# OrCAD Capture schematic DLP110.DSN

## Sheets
1 PAGE-10 Important Notice
2 PAGE-09 Rev History
3 PAGE-01  TITLE: rev: D
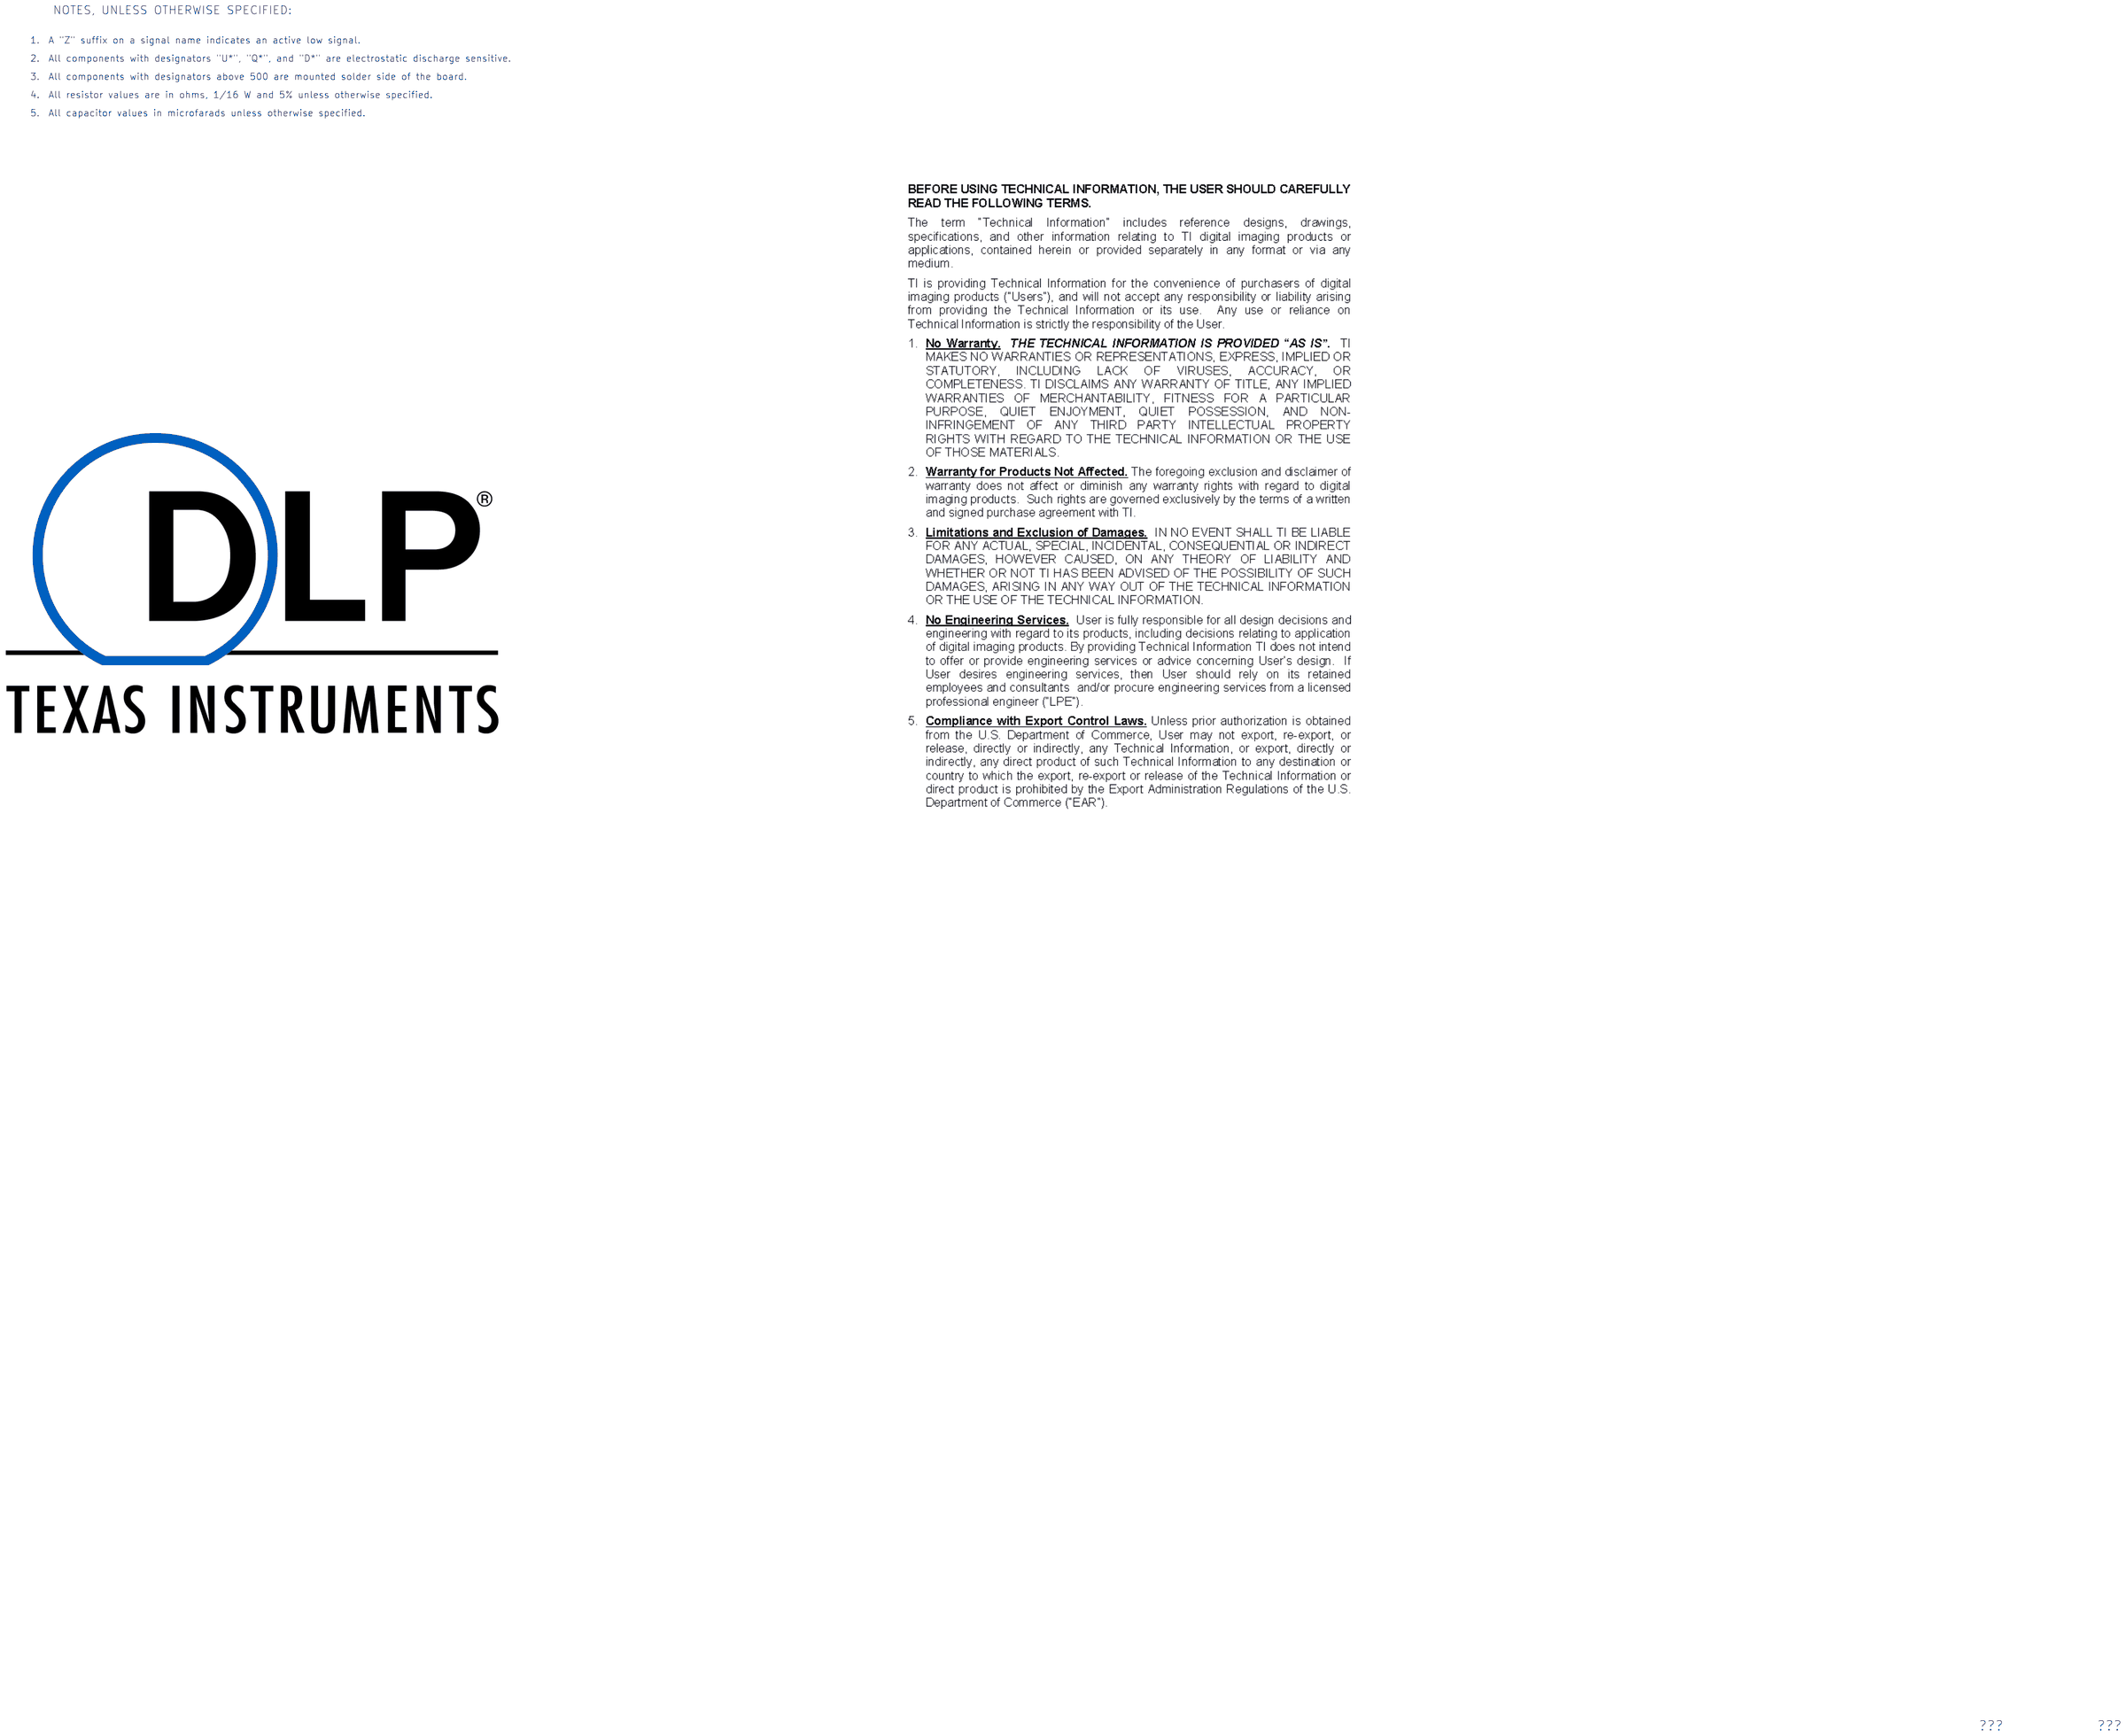
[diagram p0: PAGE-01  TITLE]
4 PAGE-02  BLOCK DIAGRAM
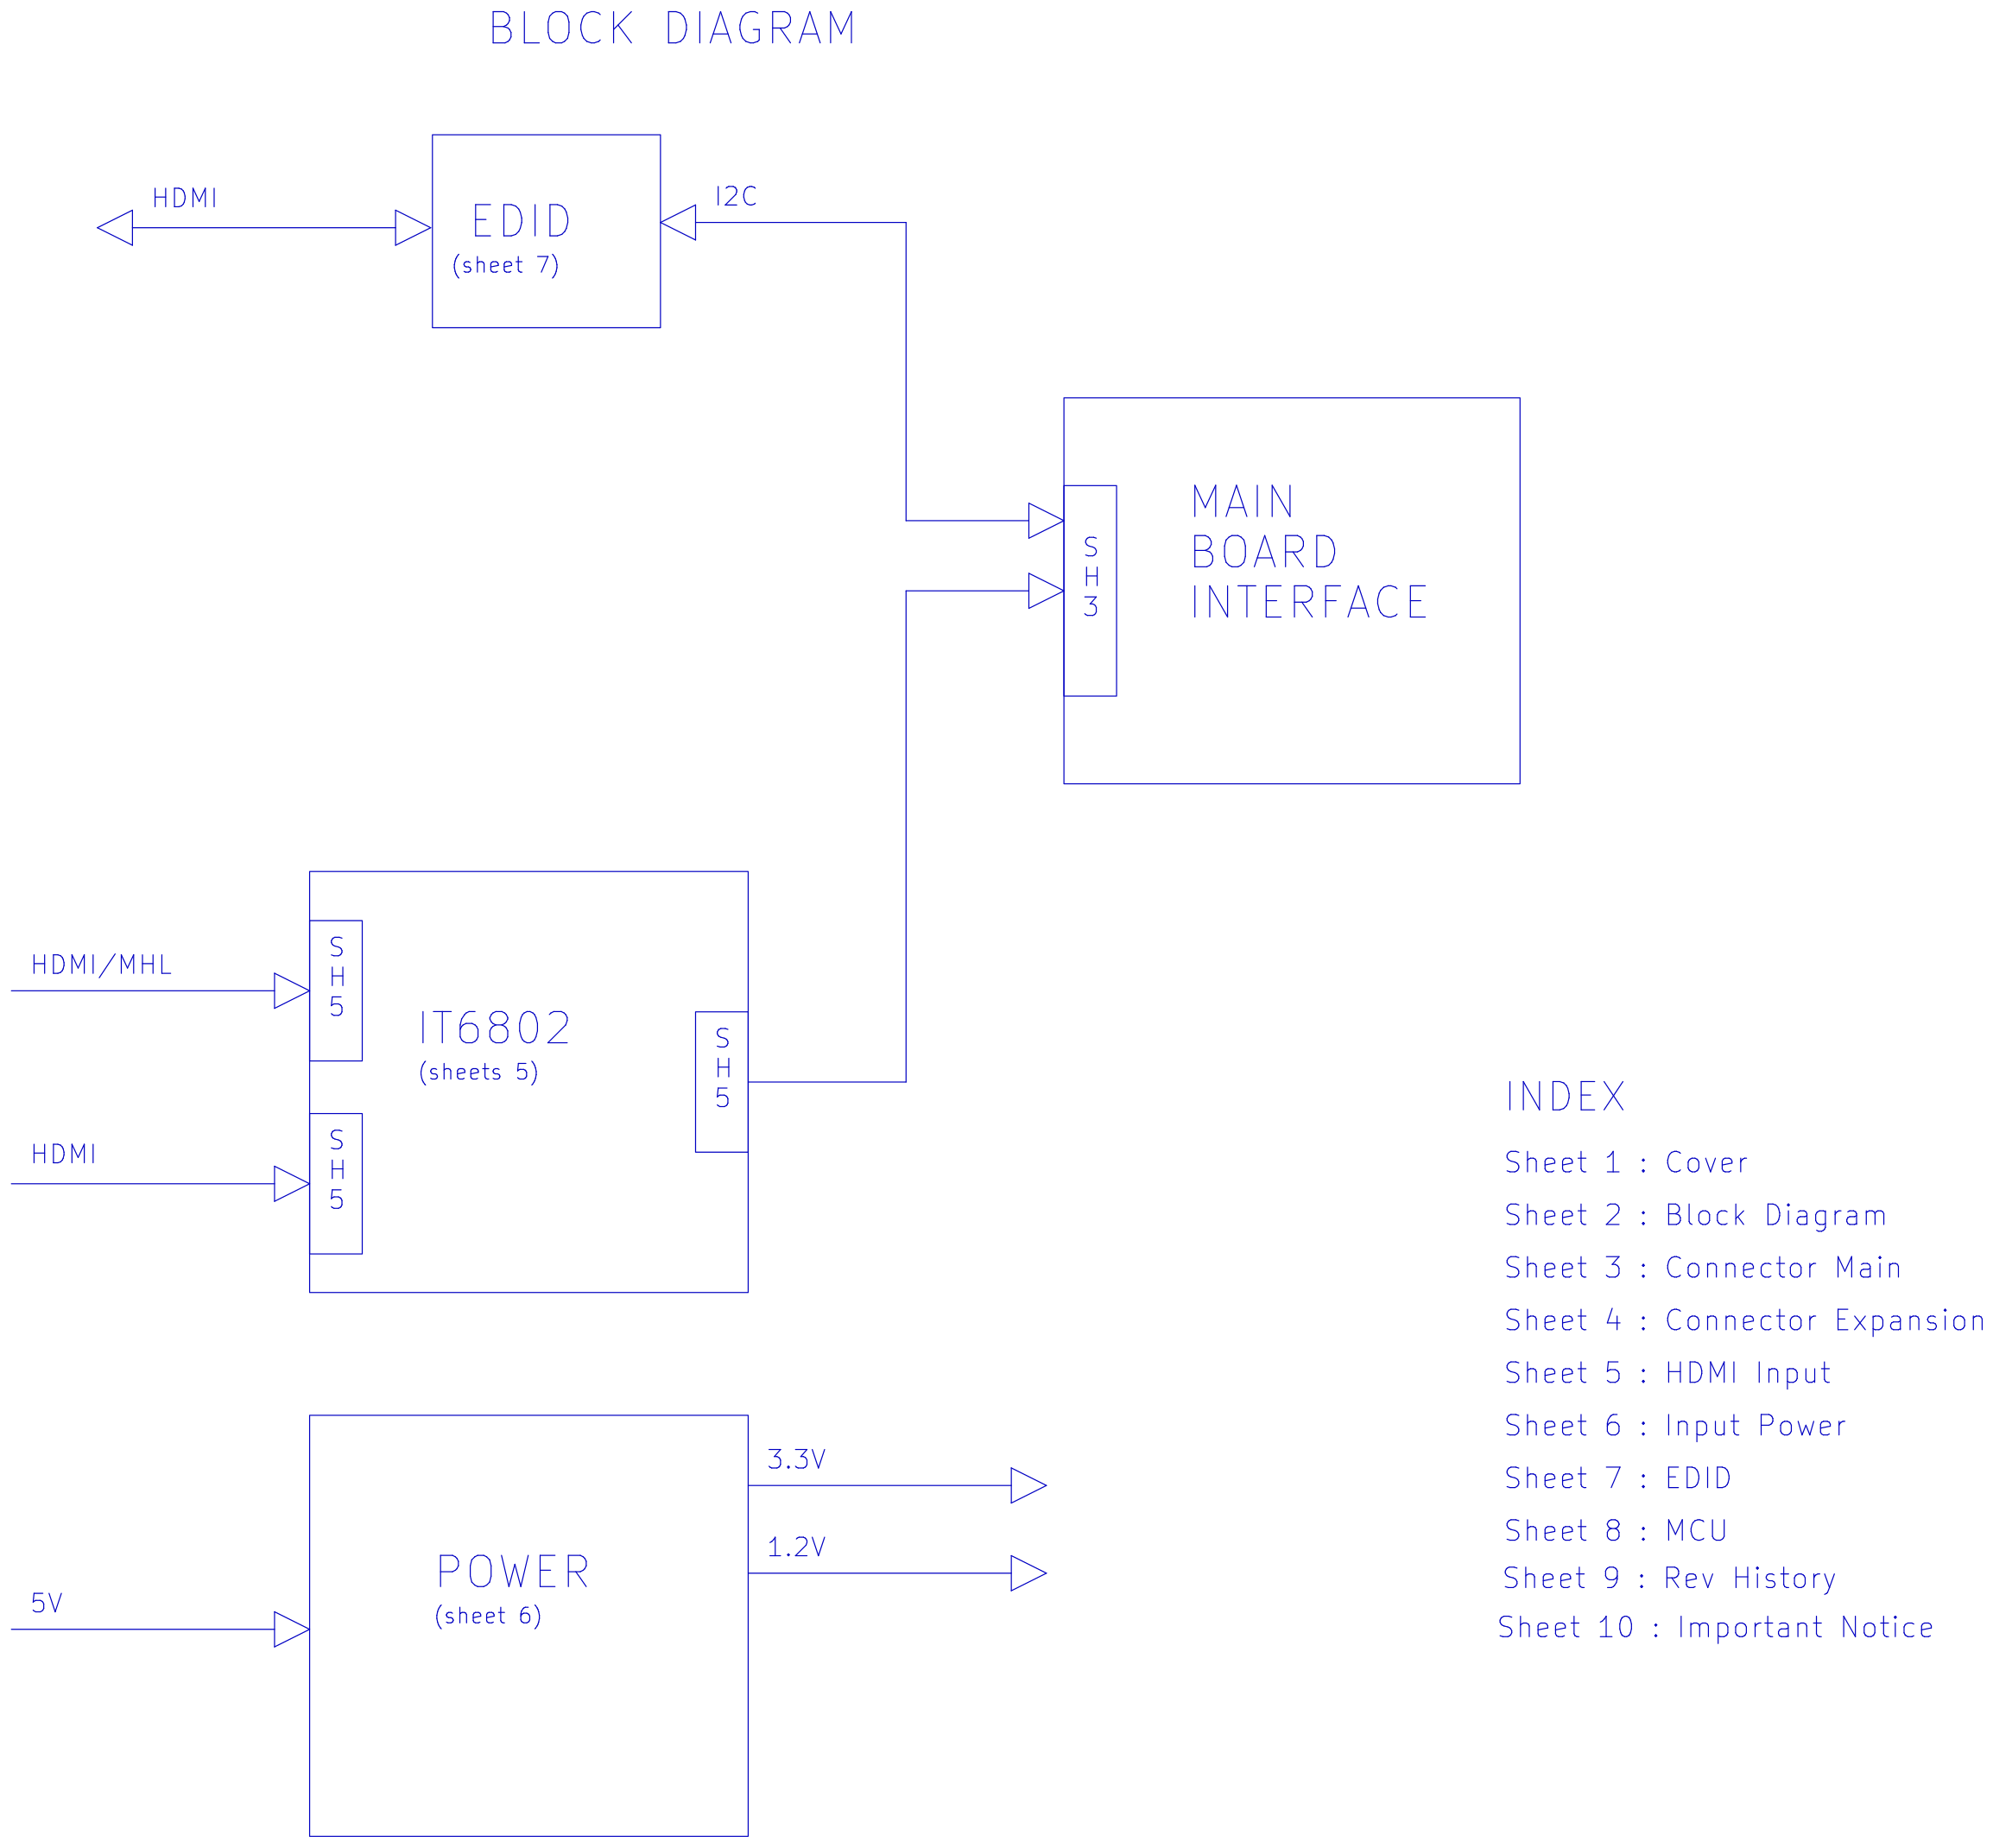
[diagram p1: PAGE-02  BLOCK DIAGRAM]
5 PAGE-03  CONNECTOR MAIN: size A3
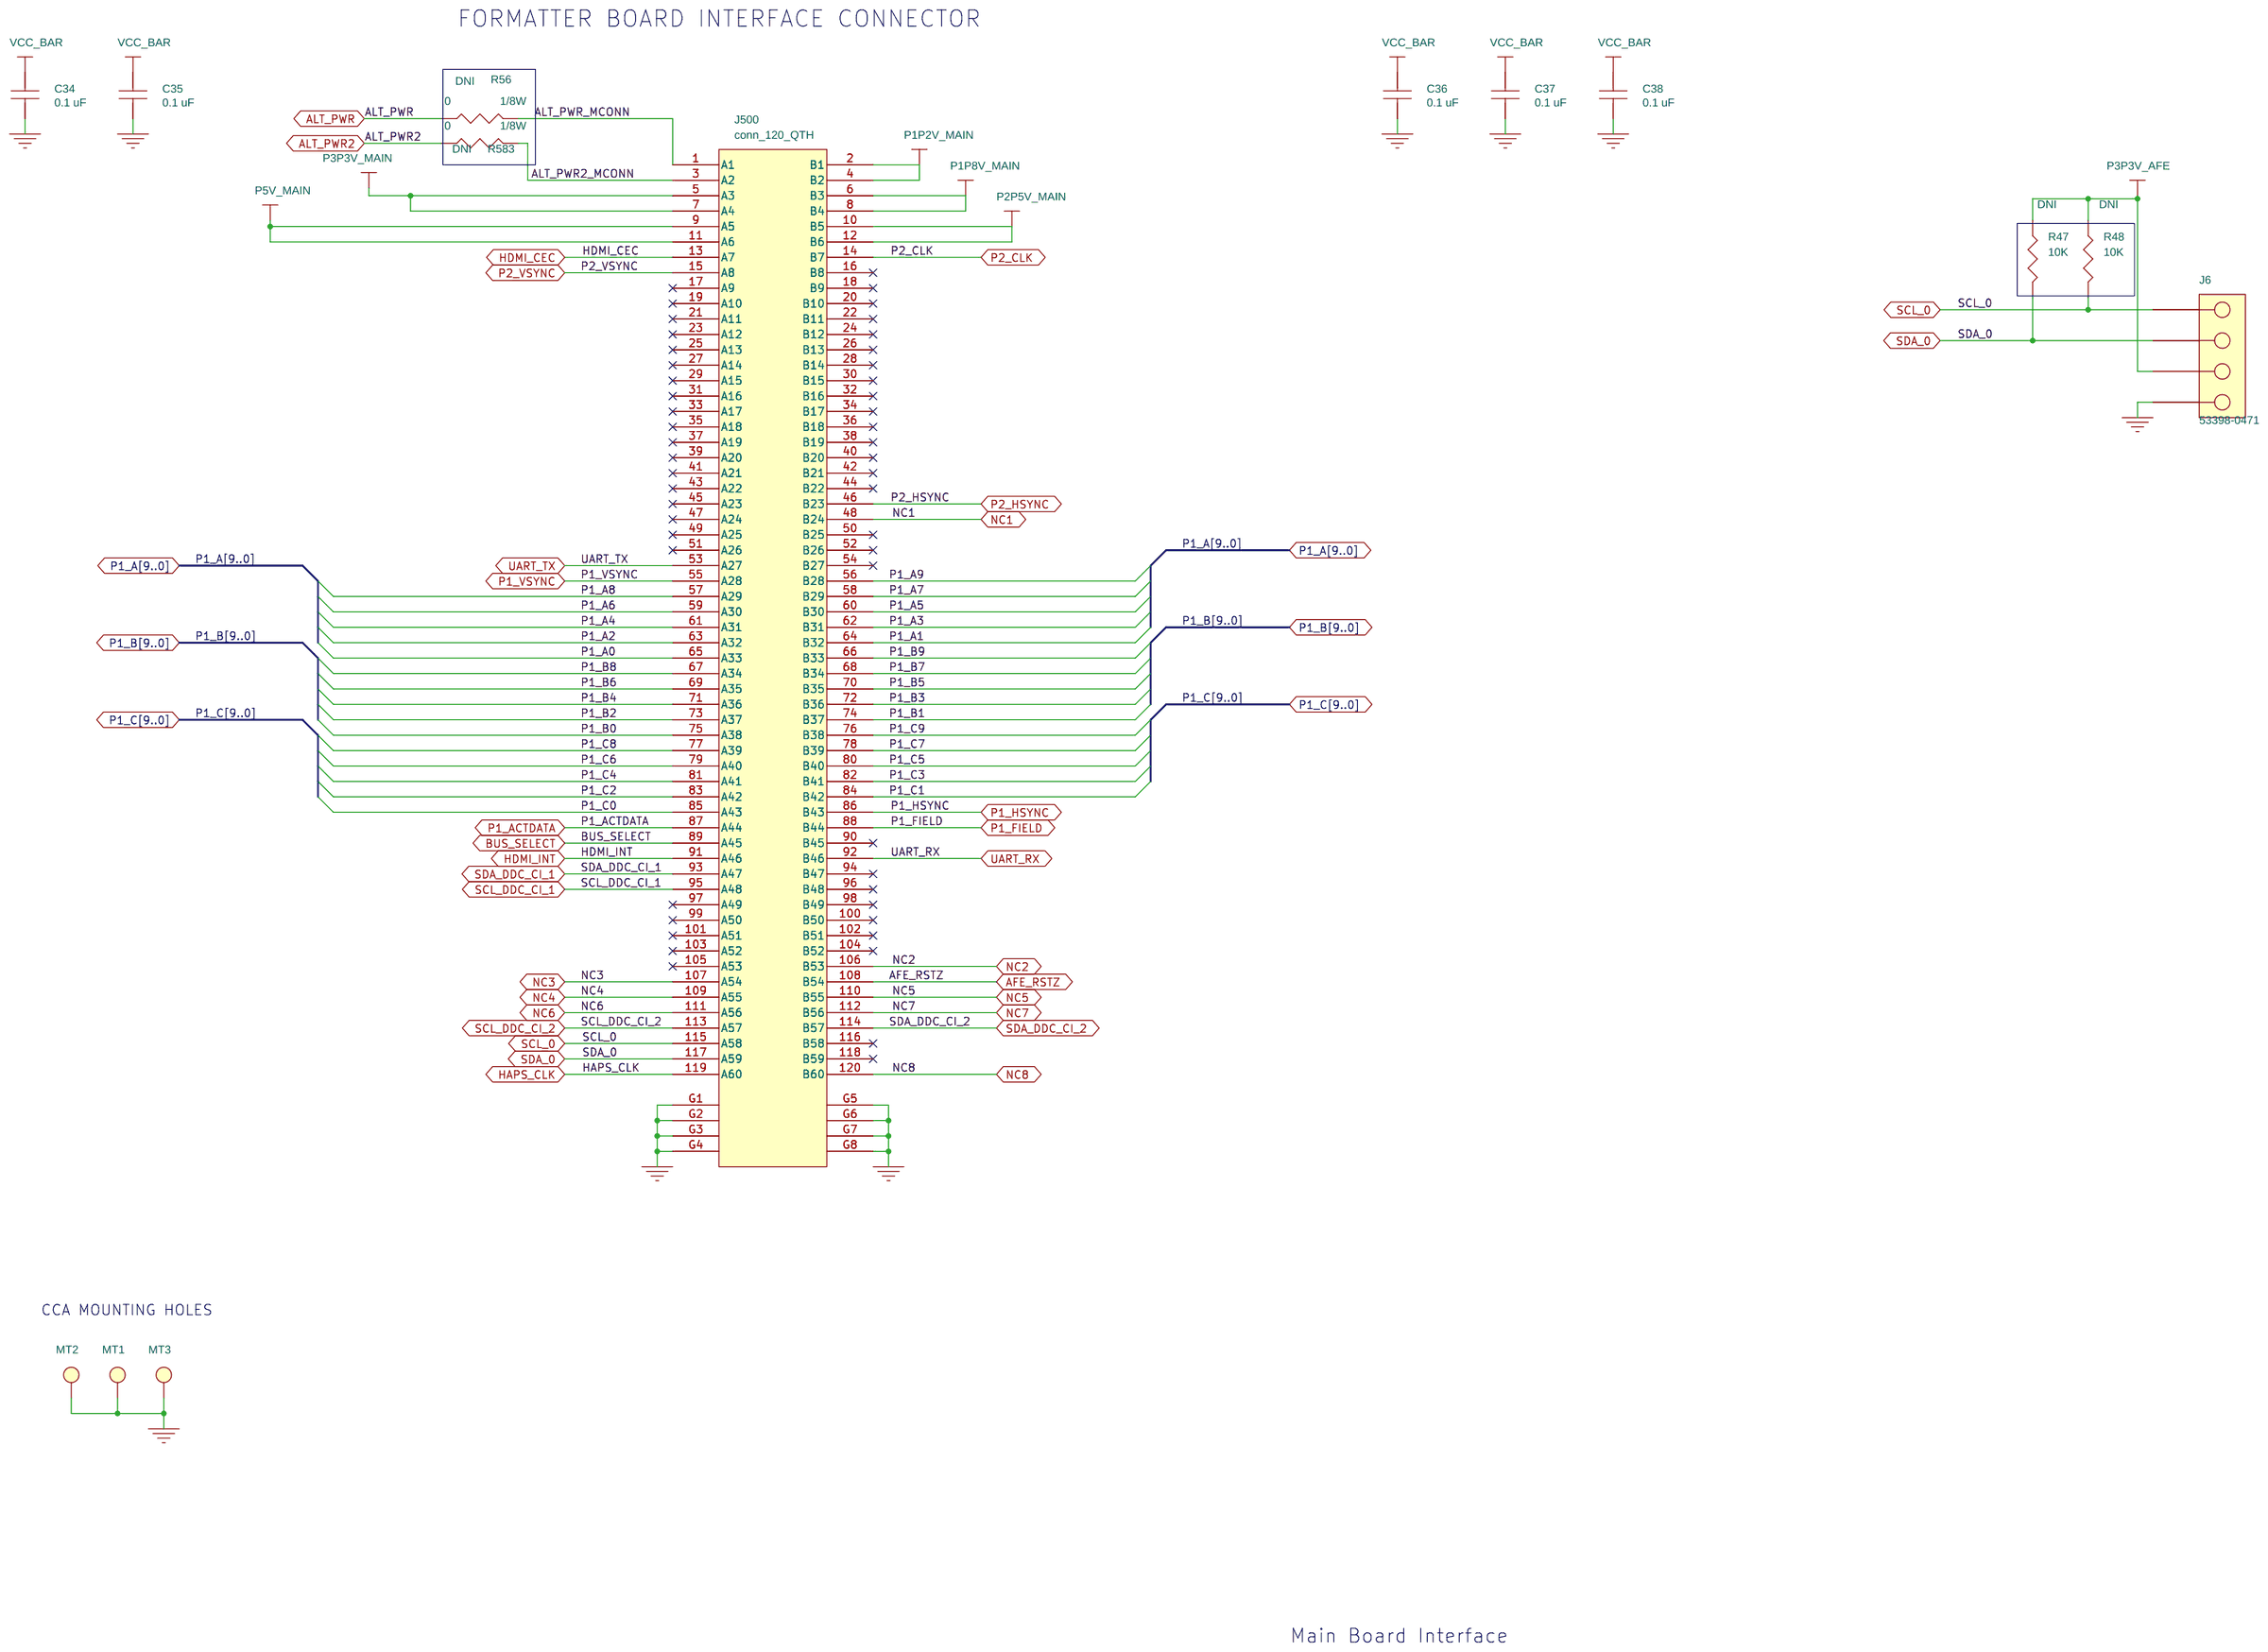
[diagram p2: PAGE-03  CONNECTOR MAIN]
6 PAGE-04  CONNECTOR EXPANSION: size A3
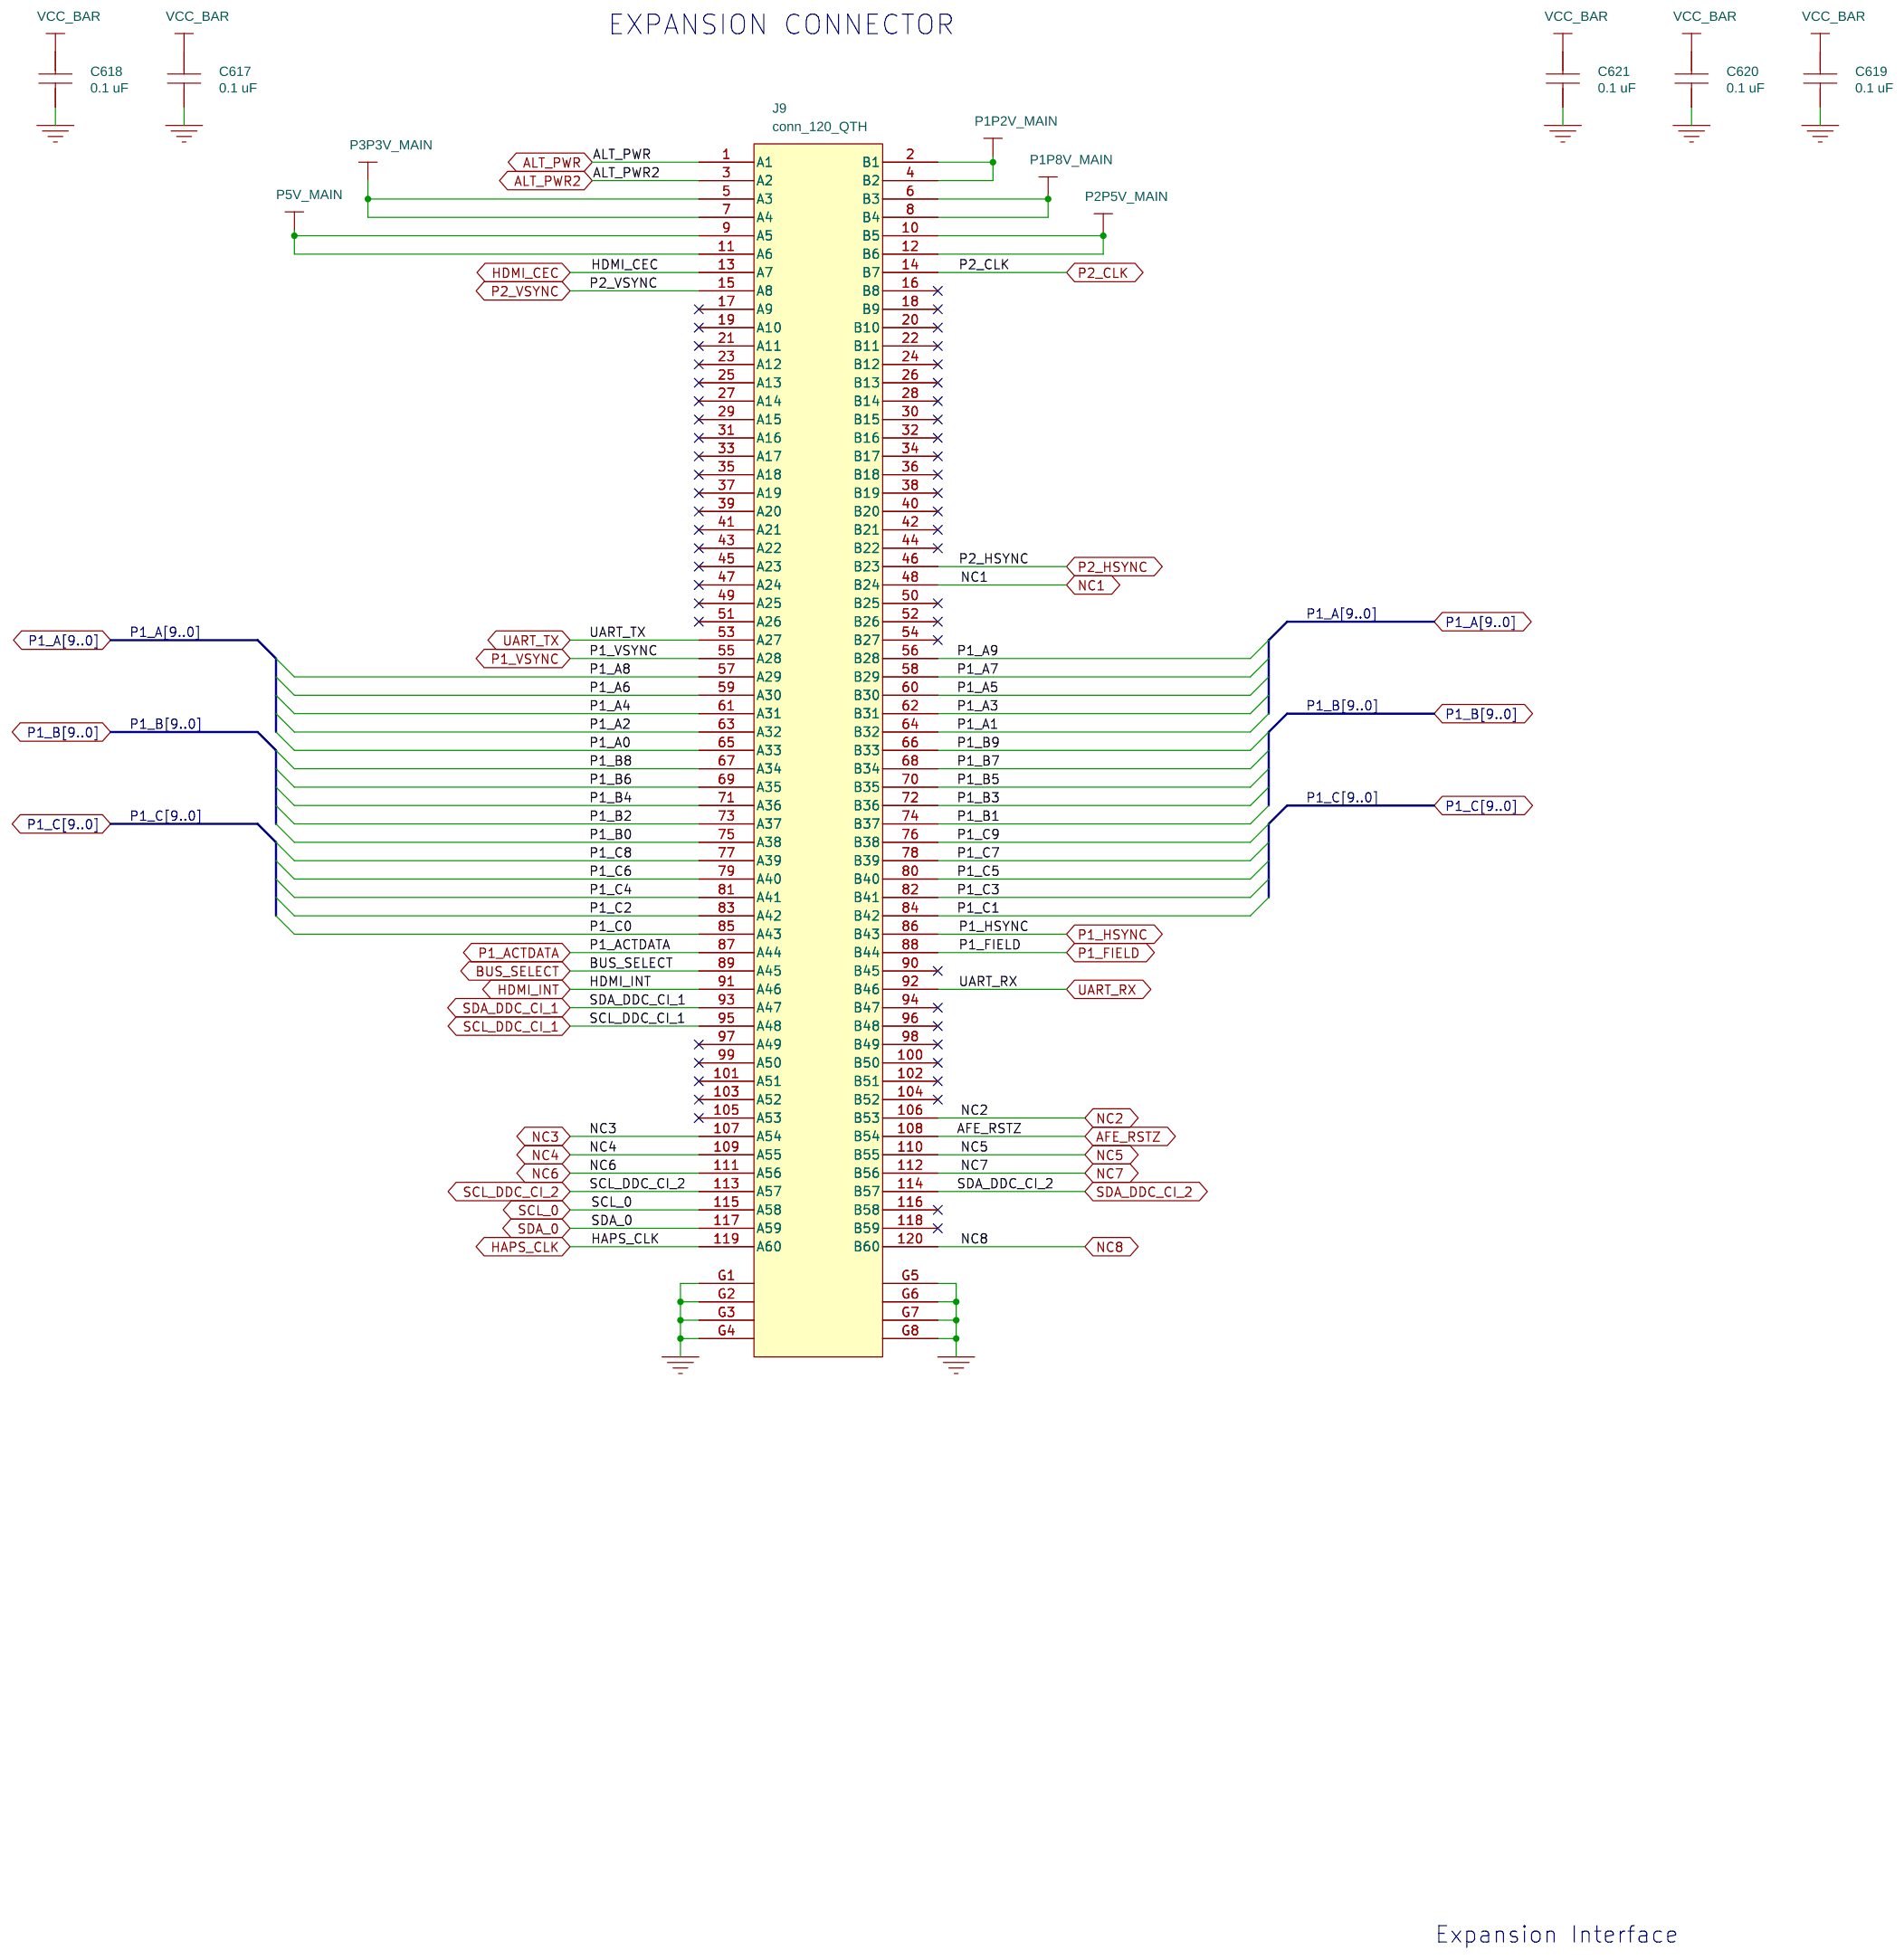
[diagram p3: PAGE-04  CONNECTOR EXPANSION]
7 PAGE-05  HDMI INPUT: size C
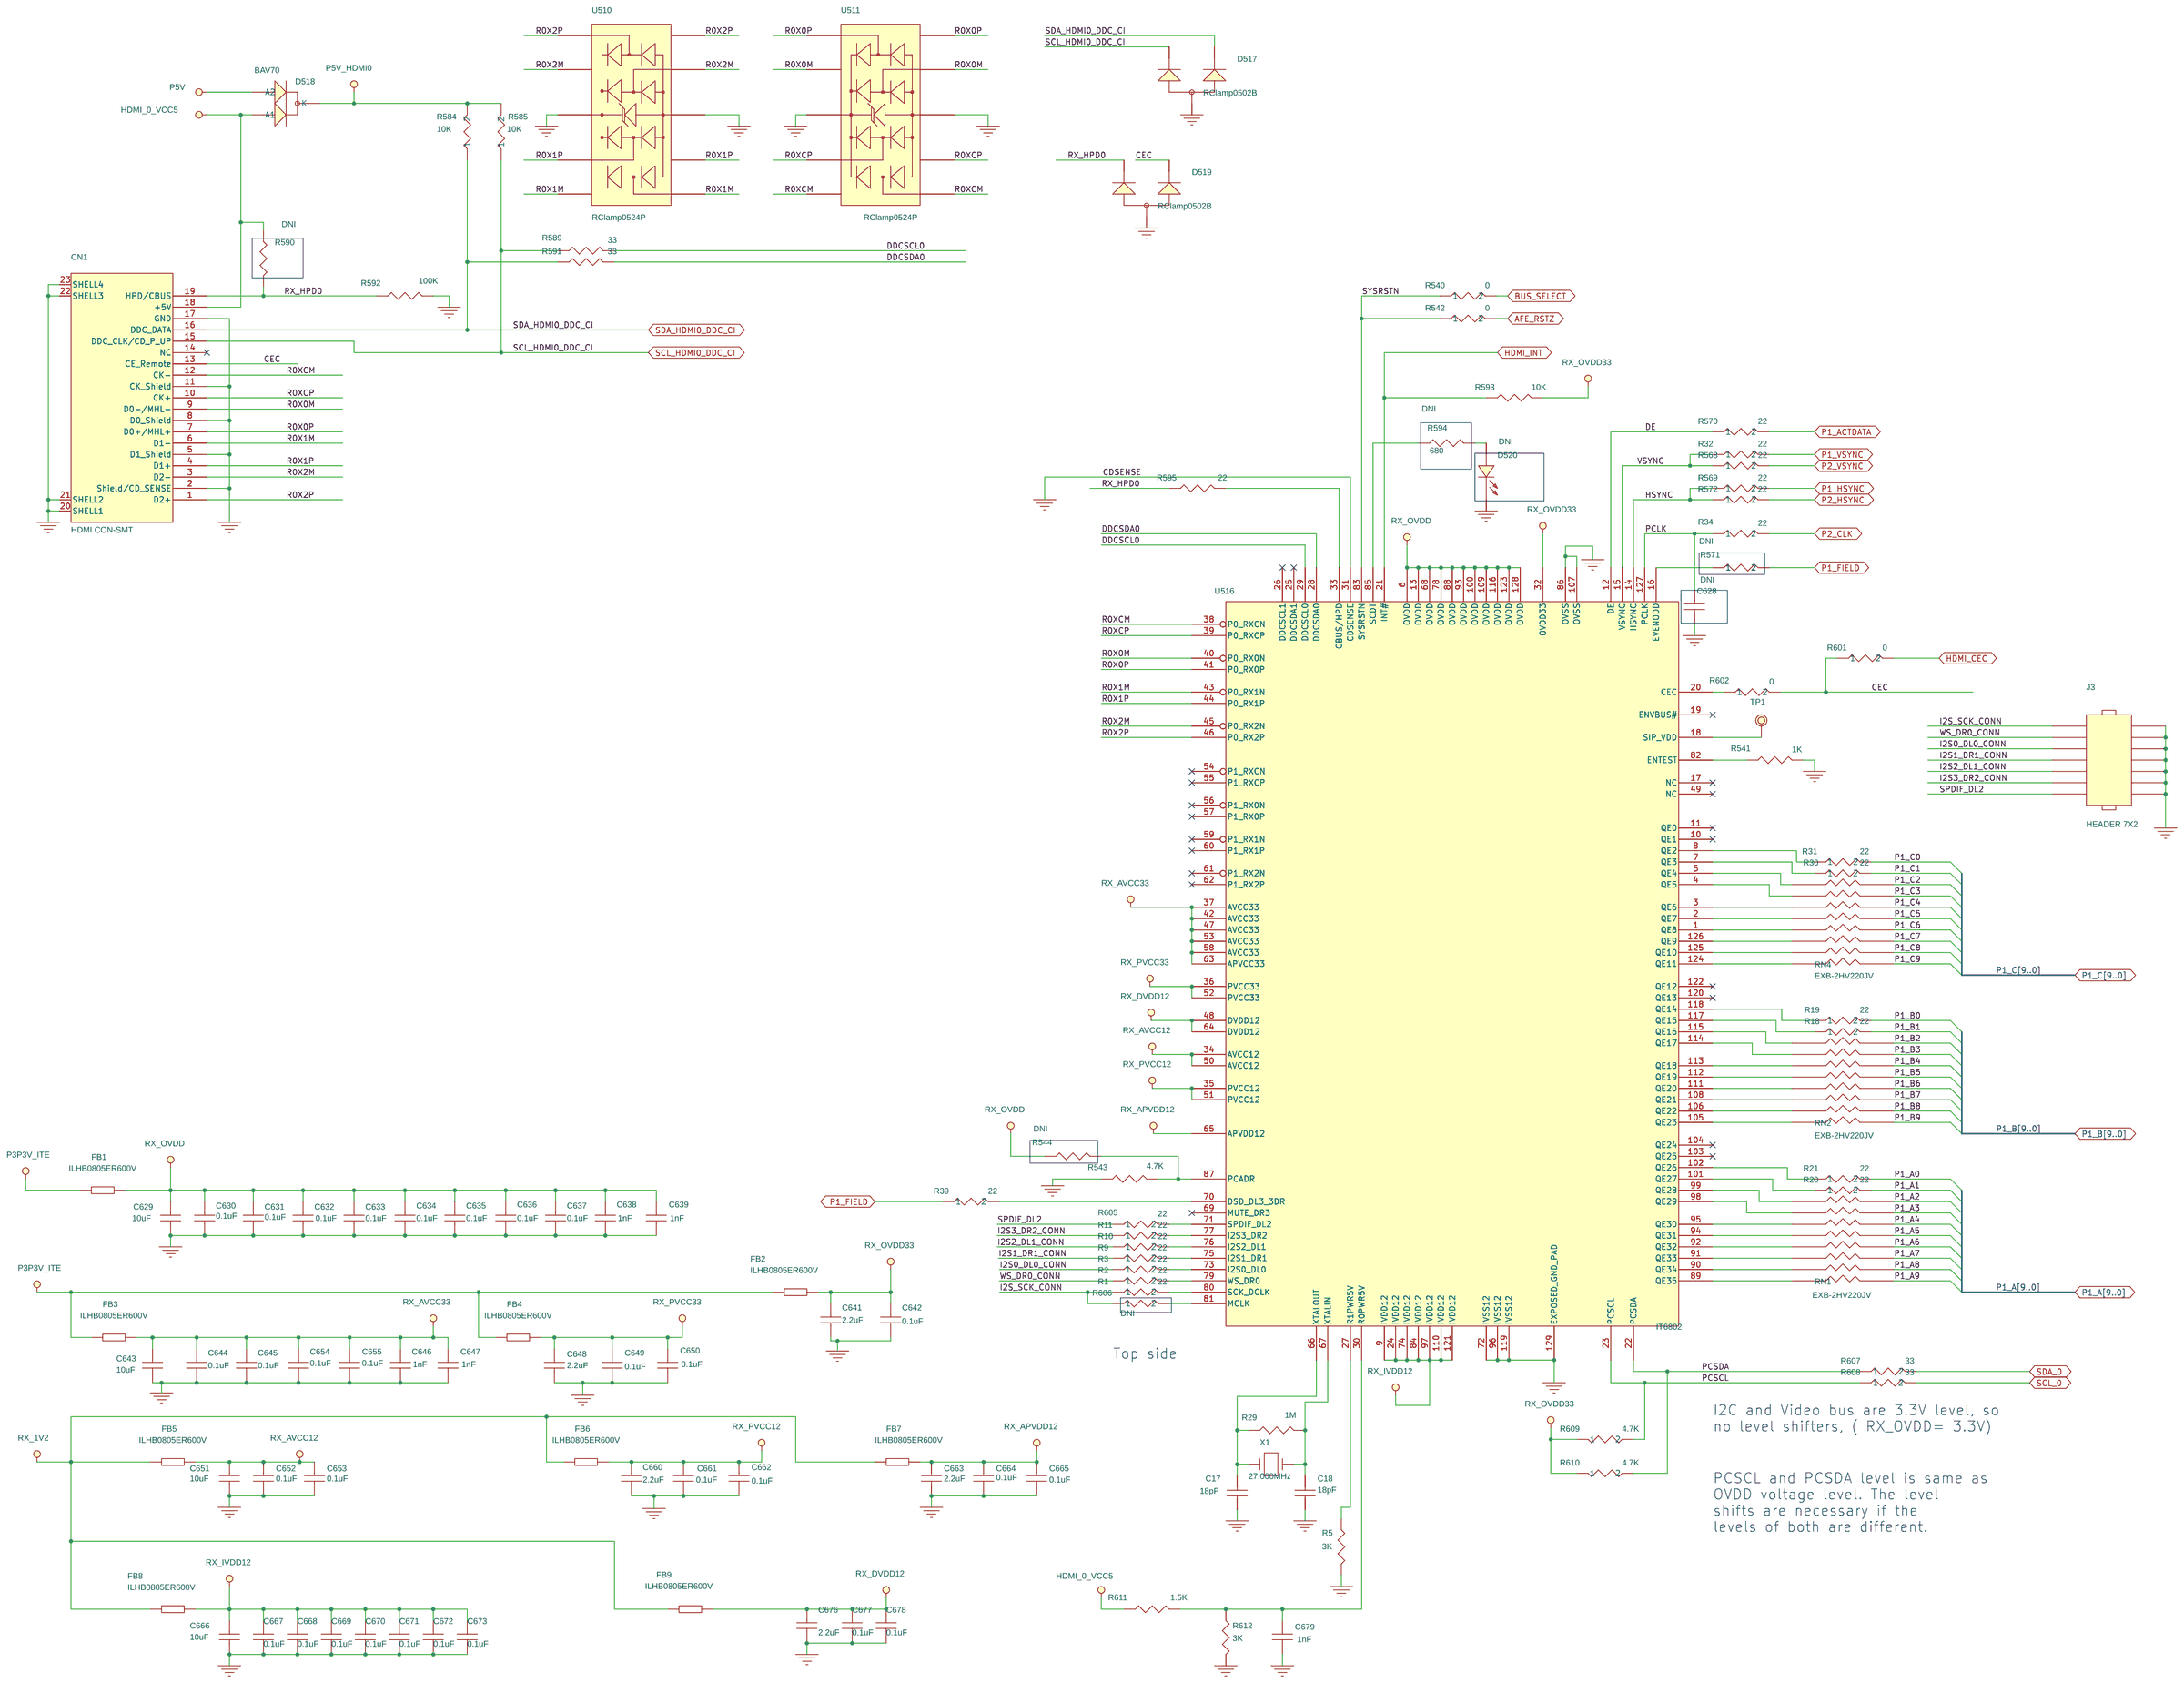
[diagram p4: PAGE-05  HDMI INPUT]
8 PAGE-06  INPUT POWER: size A3
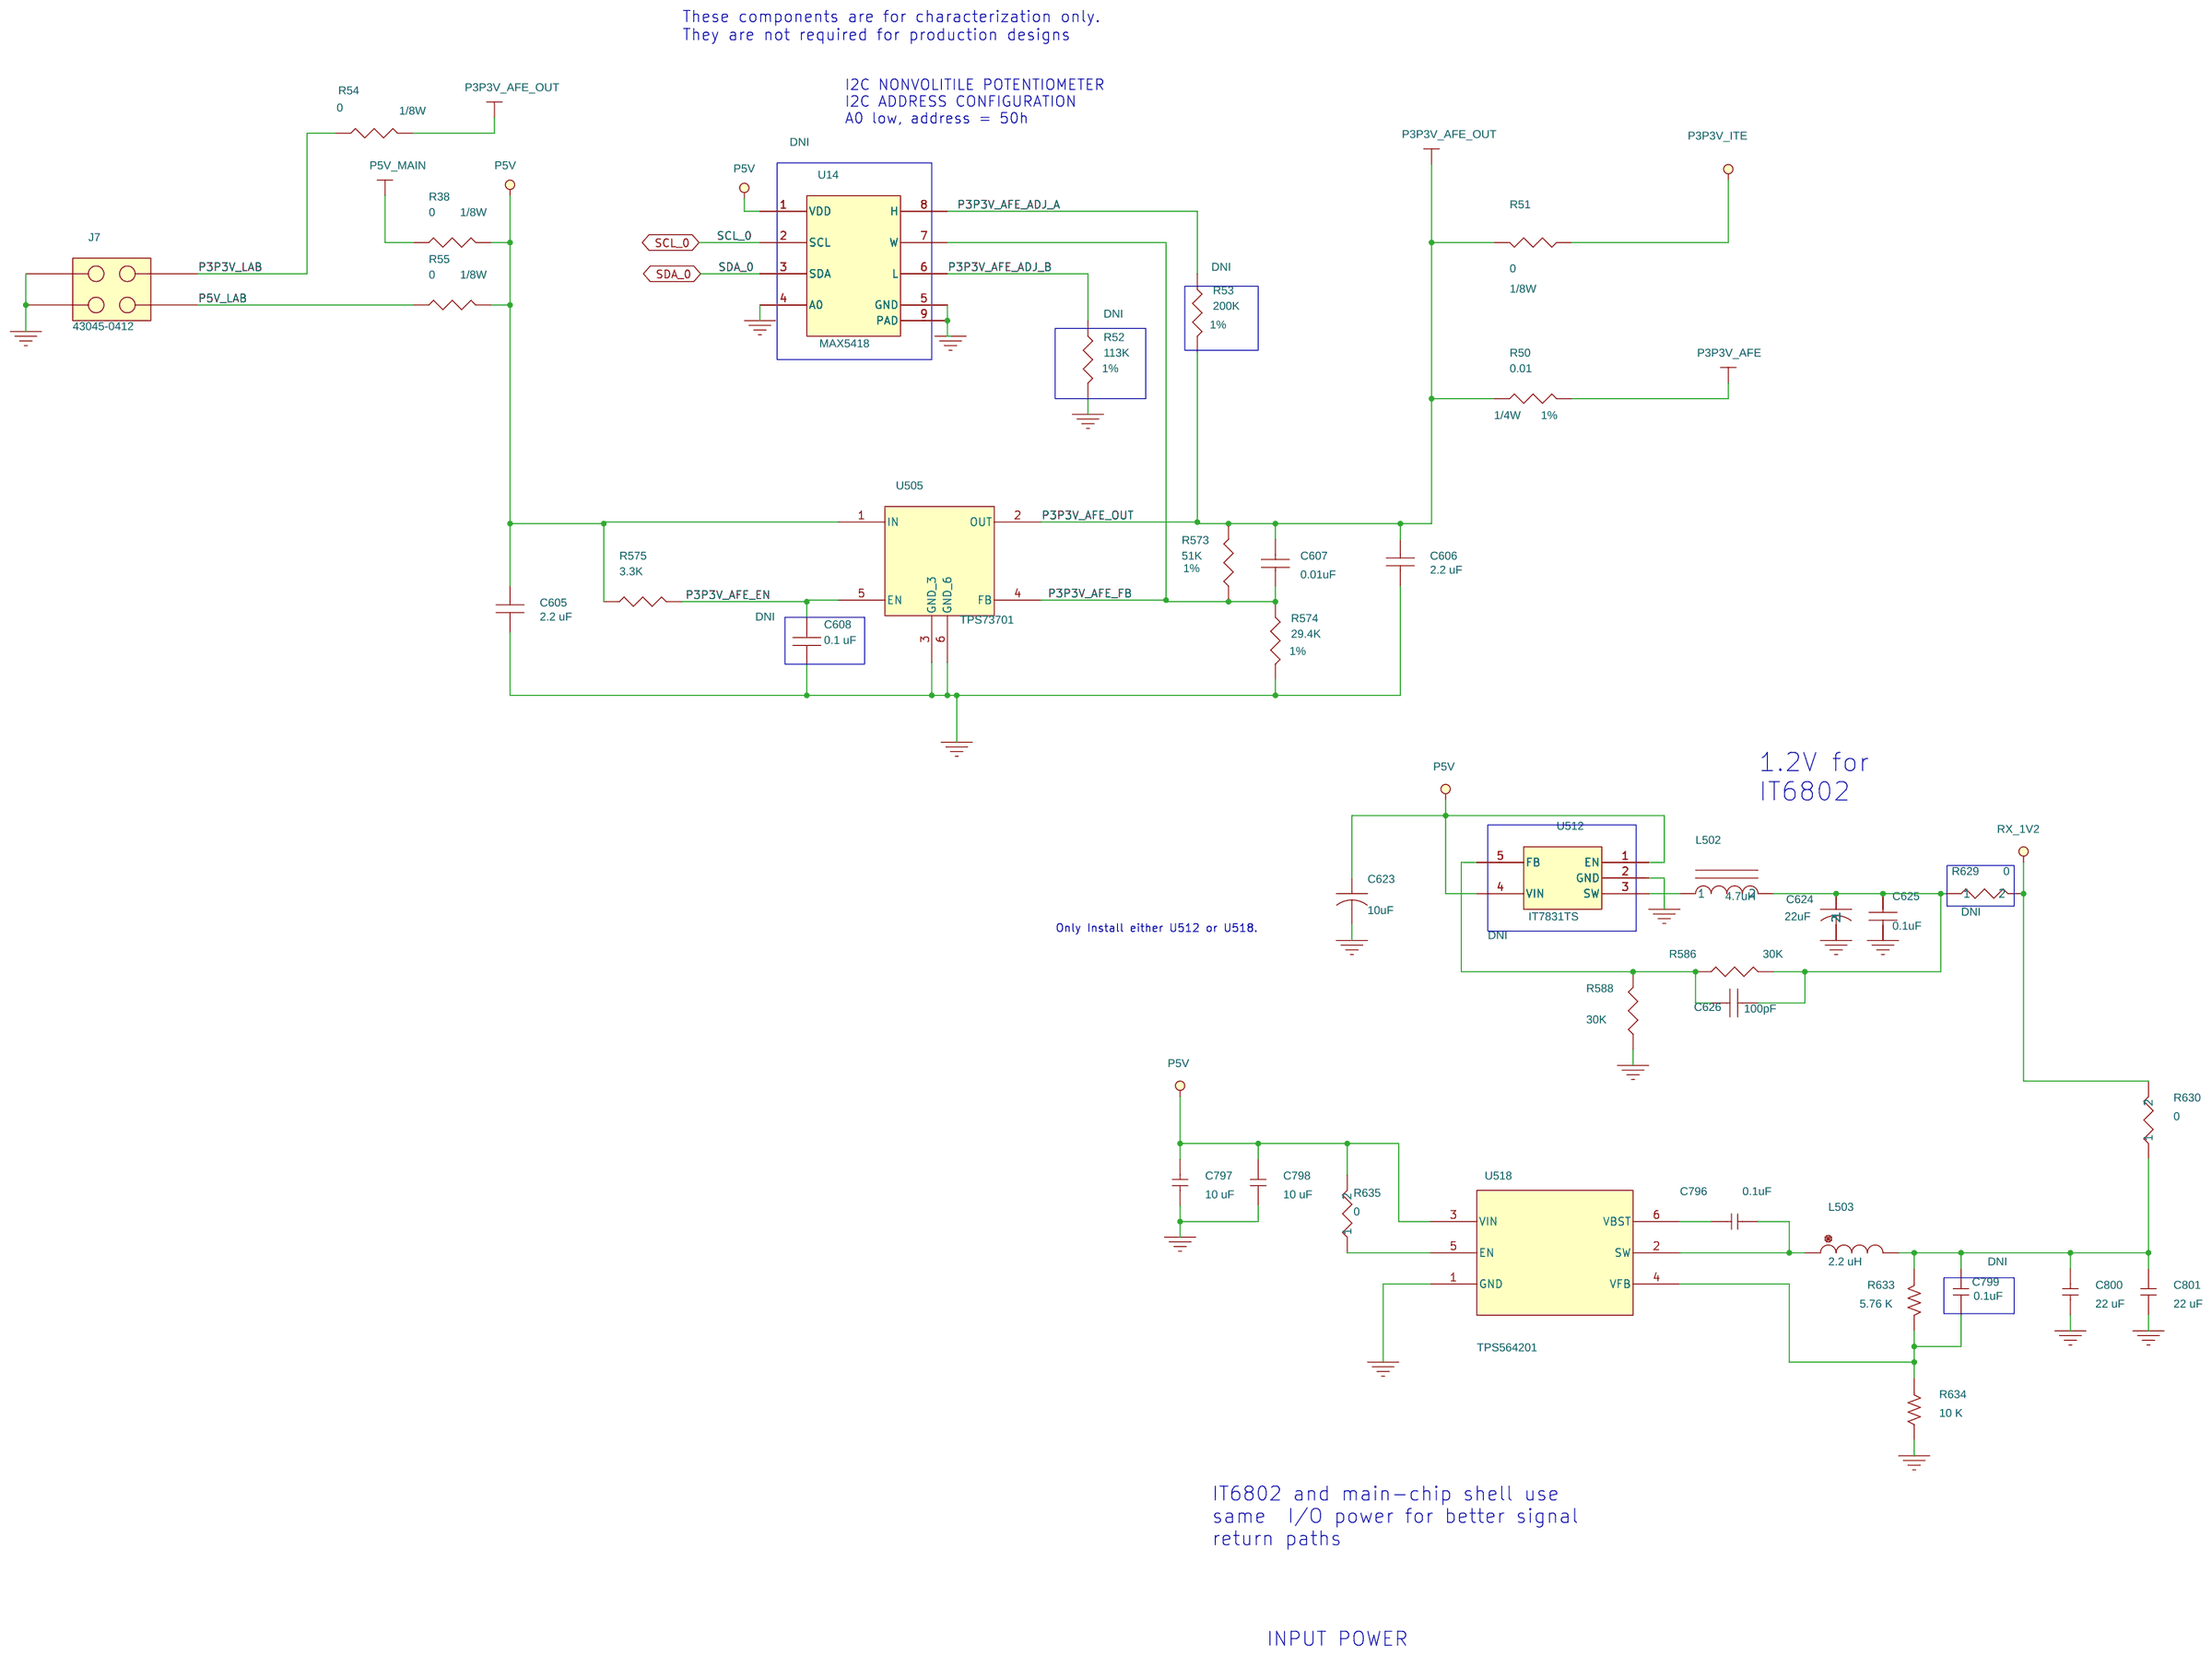
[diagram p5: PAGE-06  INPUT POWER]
9 PAGE-07  EDID: size A3
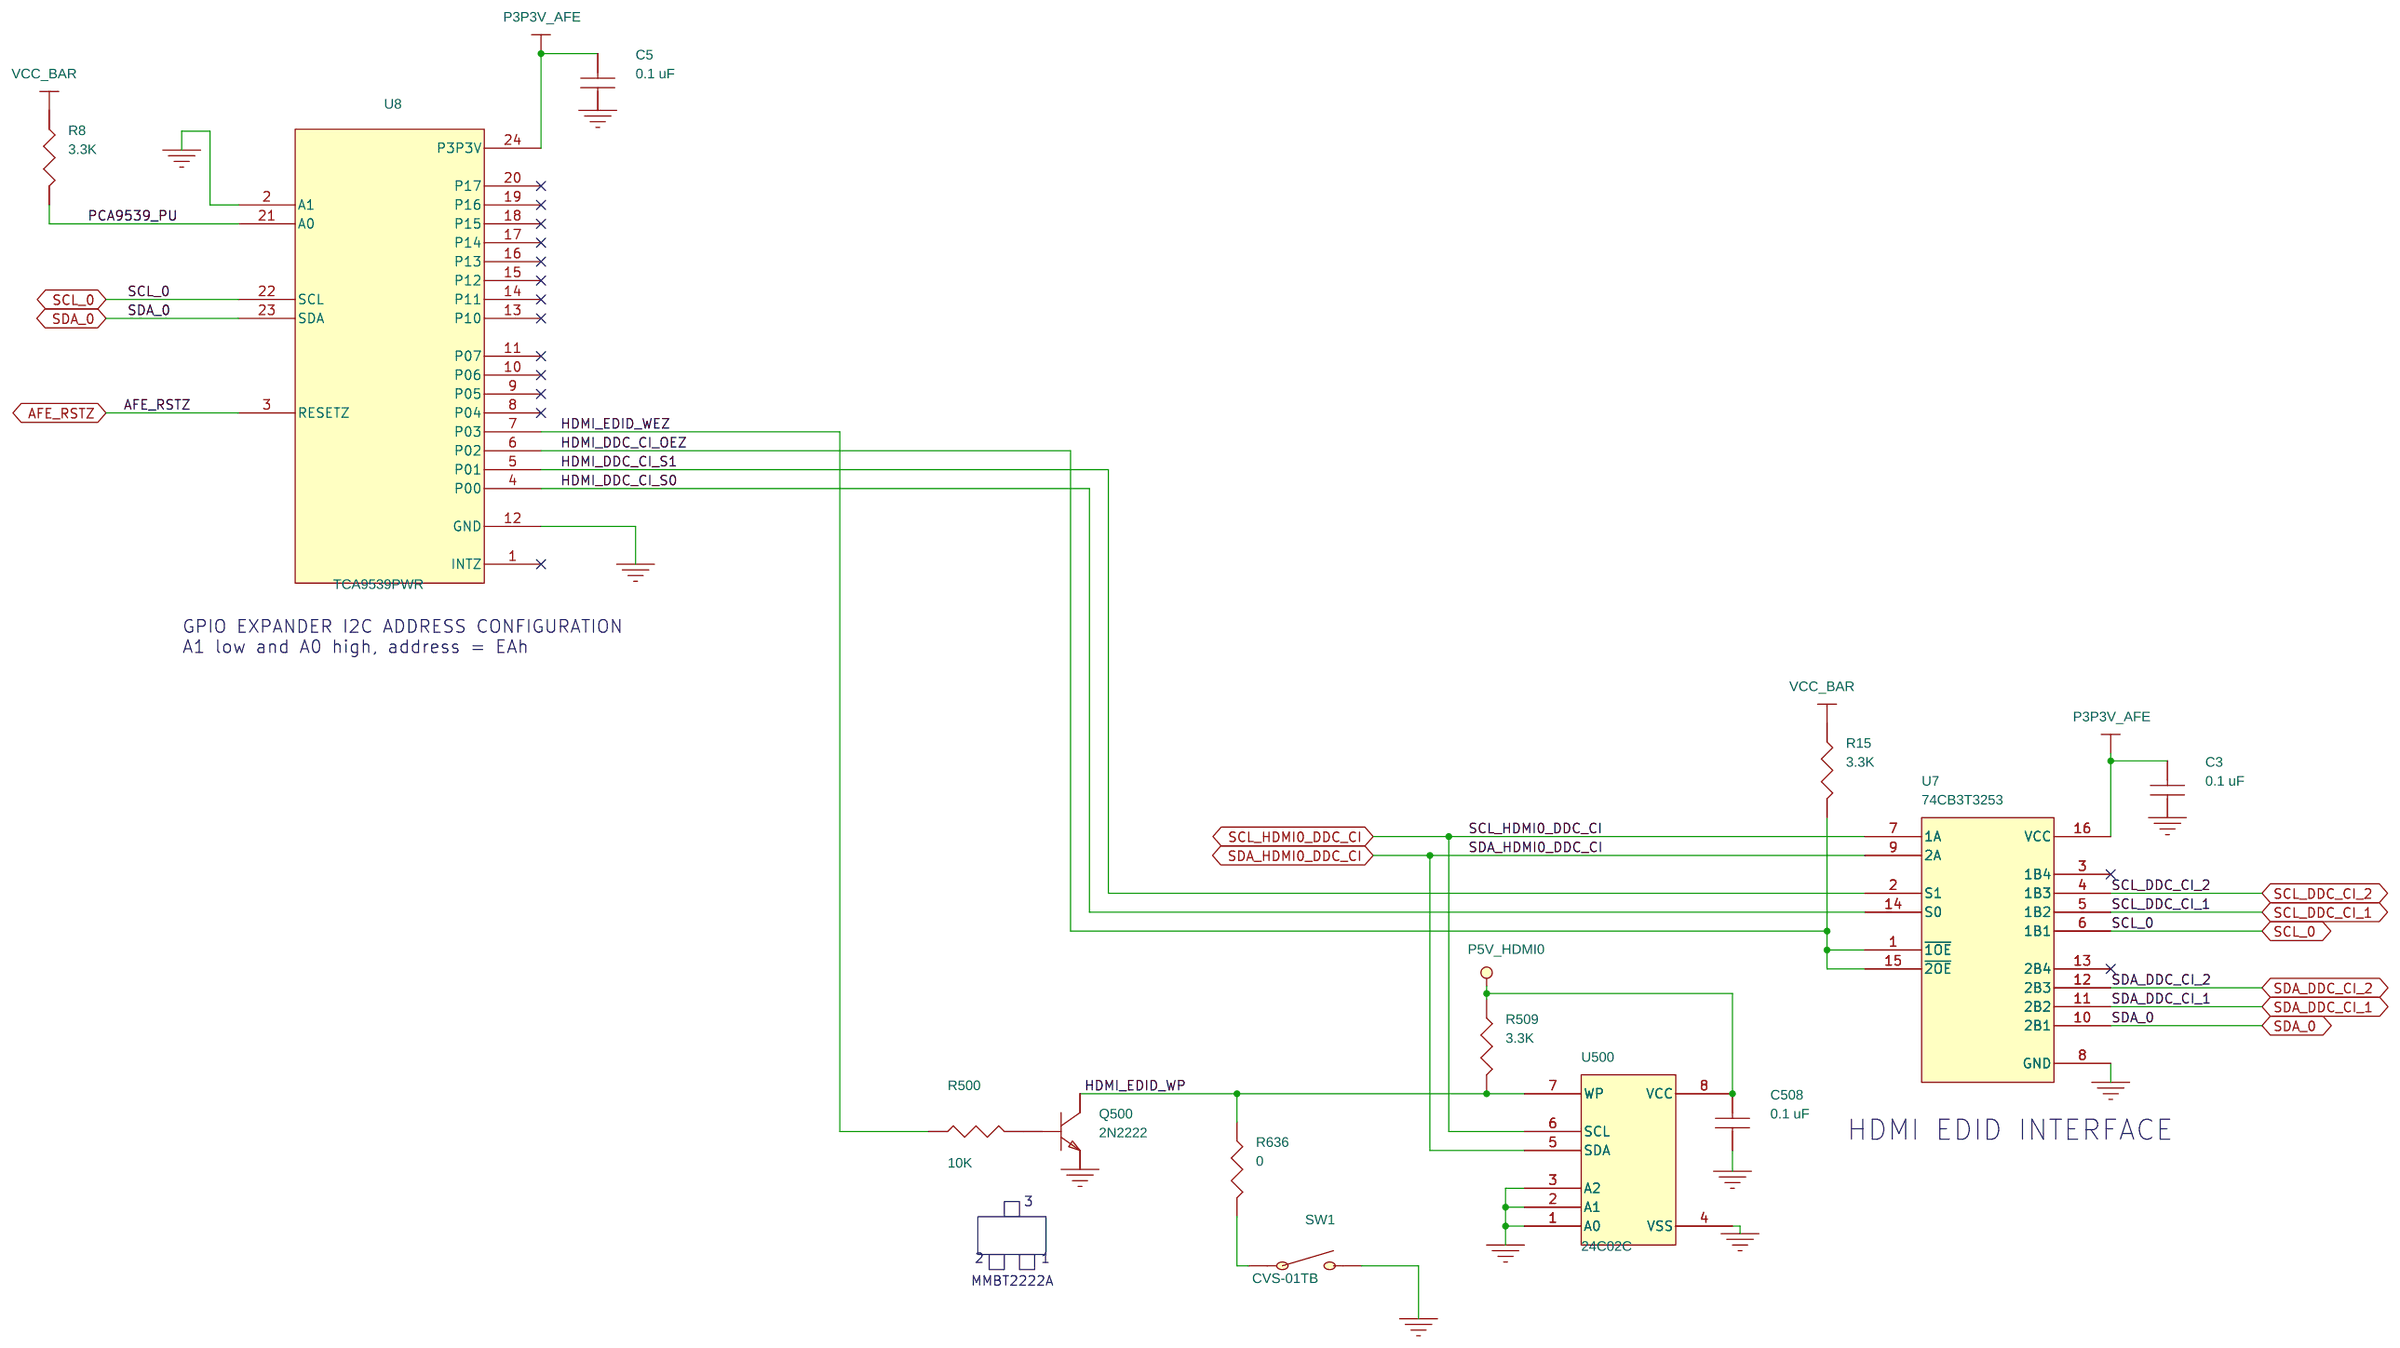
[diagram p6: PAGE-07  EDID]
10 PAGE-08 MCU: size B
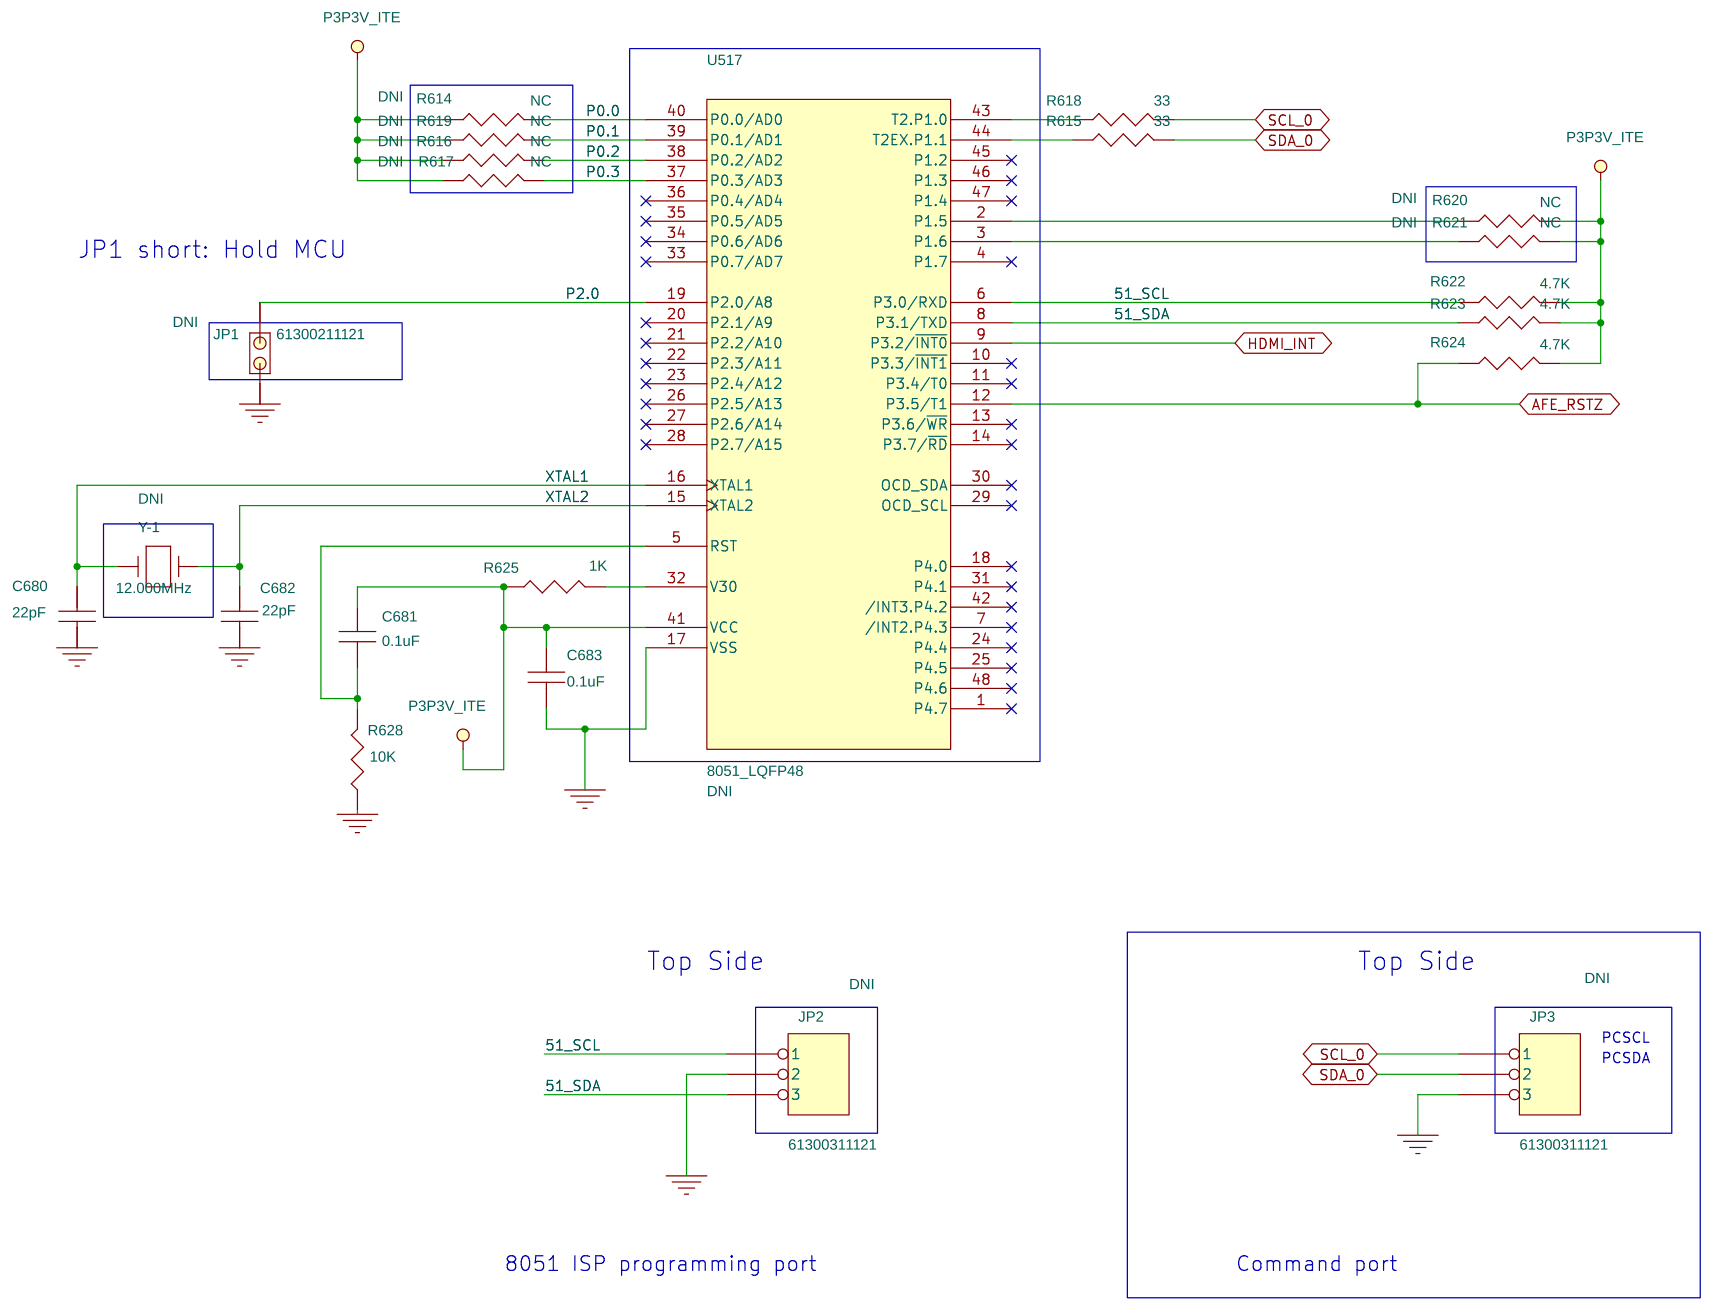
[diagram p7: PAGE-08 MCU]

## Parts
sheet PAGE-03  CONNECTOR MAIN
C34  0.1 uF  [CAP_0402]
C35  0.1 uF  [CAP_0402]
C36  0.1 uF  [CAP_0402]
C37  0.1 uF  [CAP_0402]
C38  0.1 uF  [CAP_0402]
J6  CONN_4  [CONN_4]
J500  conn_120_QTH  [QSH_120]
MT1  MOUNTING HOLE  [MH276-157GND]
MT2  MOUNTING HOLE  [MH276-157GND]
MT3  MOUNTING HOLE  [MH276-157GND]
R47  10K  [RES_0402]
R48  10K  [RES_0402]
R56  0  [RES_0805]
R583  0  [RES_0805]
sheet PAGE-04  CONNECTOR EXPANSION
C617  0.1 uF  [CAP_0402]
C618  0.1 uF  [CAP_0402]
C619  0.1 uF  [CAP_0402]
C620  0.1 uF  [CAP_0402]
C621  0.1 uF  [CAP_0402]
J9  conn_120_QTH  [QTH_120]
sheet PAGE-05  HDMI INPUT
C17  18pF  [C0603]
C18  18pF  [C0603]
C628  NC  [C0603]
C629  10uF  [C1206]
C630  0.1uF  [C0603]
C631  0.1uF  [C0603]
C632  0.1uF  [C0603]
C633  0.1uF  [C0603]
C634  0.1uF  [C0603]
C635  0.1uF  [C0603]
C636  0.1uF  [C0603]
C637  0.1uF  [C0603]
C638  1nF  [C0603]
C639  1nF  [C0603]
C641  2.2uF  [C0603]
C642  0.1uF  [C0603]
C643  10uF  [C1206]
C644  0.1uF  [C0603]
C645  0.1uF  [C0603]
C646  1nF  [C0603]
C647  1nF  [C0603]
C648  2.2uF  [C0603]
C649  0.1uF  [C0603]
C650  0.1uF  [C0603]
C651  10uF  [C1206]
C652  0.1uF  [C0603]
C653  0.1uF  [C0603]
C654  0.1uF  [C0603]
C655  0.1uF  [C0603]
C660  2.2uF  [C0603]
C661  0.1uF  [C0603]
C662  0.1uF  [C0603]
C663  2.2uF  [C0603]
C664  0.1uF  [C0603]
C665  0.1uF  [C0603]
C666  10uF  [C1206]
C667  0.1uF  [C0603]
C668  0.1uF  [C0603]
C669  0.1uF  [C0603]
C670  0.1uF  [C0603]
C671  0.1uF  [C0603]
C672  0.1uF  [C0603]
C673  0.1uF  [C0603]
C676  2.2uF  [C0603]
C677  0.1uF  [C0603]
C678  0.1uF  [C0603]
C679  1nF  [C0603]
CN1  HDMI CON-SMT  [HDMI-19P]
D517  RClamp0502B  [SOT-523]
D518  BAV70  [SOT23B]
D519  RClamp0502B  [SOT-523]
D520  NC/ LED  [led0603]
FB1  ILHB0805ER600V  [FB0805]
FB2  ILHB0805ER600V  [FB0805]
FB3  ILHB0805ER600V  [FB0805]
FB4  ILHB0805ER600V  [FB0805]
FB5  ILHB0805ER600V  [FB0805]
FB6  ILHB0805ER600V  [FB0805]
FB7  ILHB0805ER600V  [FB0805]
FB8  ILHB0805ER600V  [FB0805]
FB9  ILHB0805ER600V  [FB0805]
J3  HEADER 7X2
R1  22  [R0603]
R2  22  [R0603]
R3  22  [R0603]
R5  3K  [R0603]
R9  22  [R0603]
R10  22  [R0603]
R11  22  [R0603]
R18  22  [R0603]
R19  22  [R0603]
R20  22  [R0603]
R21  22  [R0603]
R29  1M  [R0603]
R30  22  [R0603]
R31  22  [R0603]
R32  22  [R0603]
R34  22  [R0603]
R39  22  [R0603]
R540  0  [R0603]
R541  1K  [R0603]
R542  0  [R0603]
R543  4.7K  [R0603]
R544  NC  [R0603]
R568  22  [R0603]
R569  22  [R0603]
R570  22  [R0603]
R571  NC  [R0603]
R572  22  [R0603]
R584  10K  [R0603]
R585  10K  [R0603]
R589  33  [R0603]
R590  NC  [R0603]
R591  33  [R0603]
R592  100K  [R0603]
R593  10K  [R0603]
R594  680  [R0603]
R595  22  [R0603]
R601  0  [R0603]
R602  0  [R0603]
R605  22  [R0603]
R606  NC  [R0603]
R607  33  [R0603]
R608  33  [R0603]
R609  4.7K  [R0603]
R610  4.7K  [R0603]
R611  1.5K  [R0603]
R612  3K  [R0603]
RN1  RESARR_IS_8/SO
RN2  RESARR_IS_8/SO
RN4  RESARR_IS_8/SO
TP1  Not-A-Part  [S-ICT30]
U510  RClamp0524P  [SLP2510P8]
U511  RClamp0524P  [SLP2510P8]
U516  IT6802  [LQFP-128 with GND PAD]
X1  27.000MHz  [SBX49SM]
sheet PAGE-06  INPUT POWER
C605  2.2 uF  [CAP_0603]
C606  2.2 uF  [CAP_0603]
C607  0.01uF  [CAP_0402]
C608  0.1 uF  [CAP_0402]
C623  10uF  [C1206]
C624  22uF  [C1206]
C625  0.1uF  [C0603]
C626  100pF  [C0603]
C796  0.1uF  [0402]
C797  10 uF  [1210]
C798  10 uF  [1210]
C799  0.1uF  [0402]
C800  22 uF  [0805]
C801  22 uF  [0805]
J7  MOLEX 3MM  [3MM_4]
L502  4.7uH  [3.6mmx3.8mm]
L503  2.2 uH  [IND-SRR1005_BOURNS]
R38  0  [RES_0805]
R50  0.01  [RES_0805]
R51  0  [RES_0805]
R52  113K  [RES_0402]
R53  200K  [RES_0402]
R54  0  [RES_0805]
R55  0  [RES_0805]
R573  51K  [RES_0402]
R574  29.4K  [RES_0402]
R575  3.3K  [RES_0402]
R586  30K  [R0603]
R588  30K  [R0603]
R629  0  [R0603]
R630  0  [R0603]
R633  5.76 K  [0402]
R634  10 K  [0402]
R635  0  [R0603]
U14  MAX5418  [TDFN_8]
U505  TPS73701  [SOT223_6]
U512  IT7831TS  [TSOT-25]
U518  TPS564201  [TSOT23-6]
sheet PAGE-07  EDID
C3  0.1 uF  [CAP_0402]
C5  0.1 uF  [CAP_0402]
C508  0.1 uF  [CAP_0402]
Q500  2N2222  [SOT-23-3]
R8  3.3K  [RES_0402]
R15  3.3K  [RES_0402]
R500  10K  [RES_0402]
R509  3.3K  [RES_0402]
R636  0  [RES_0402]
SW1  CVS-01TB  [SW_CVS-01TB_NDC]
U7  74CB3T3253  [TSSOP_16]
U8  TCA9539  [TSSOP_24]
U500  24C02C  [SOIC_8]
sheet PAGE-08 MCU
C680  22pF  [C0603]
C681  0.1uF  [C0603]
C682  22pF  [C0603]
C683  0.1uF  [C0603]
JP1  HEADER_1x2_A  [HEADER1x2/2.54]
JP2  HEADER 3  [HEADER3]
JP3  HEADER 3  [HEADER3]
R614  NC  [R0603]
R615  33  [R0603]
R616  NC  [R0603]
R617  NC  [R0603]
R618  33  [R0603]
R619  NC  [R0603]
R620  NC  [R0603]
R621  NC  [R0603]
R622  4.7K  [R0603]
R623  4.7K  [R0603]
R624  4.7K  [R0603]
R625  1K  [R0603]
R628  10K  [R0603]
U517  8051_LQFP48  [LQFP-48]
Y-1  12.000MHz  [XTAL_HC49SMT]

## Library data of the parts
C3 C5 C34-C38 C508 C617-C621 = CAP_NP: Capacitor; MFG: Samsung; Part Number: CL05B104KO3LNNC; RATING: 16V; SOURCE: DIGI PCC13490CT-ND; TOLERANCE: 10%; Type: X7R
J6 = CONN_4: Connector, 4 pin; MFG: MOLEX; Part Number: 53398-0471; SOURCE: DIGI WM7608CT-ND
J500 = conn_120_QTH: Connector, 120 pin; MFG: SAMTEC; Part Number: QSH-060-01-L-D-A; SOURCE: DIGI SAM8181-ND
MT1-MT3 = Testpoint_0: MFG: NA; Part Number: NA; SOURCE: NA
R47 R48 = R_v2: Resistor; DNI: DNI; MFG: YAGEO; Notes: DNI; Part Number: RC0402JR-0710KL; RATING: 1/16W; SOURCE: DIGI RHM10KJTR-ND; TOLERANCE: 5%
R56 R583 = R_v2: Resistor; DNI: DNI; ICA_MFR_NAME: PANASONIC; ICA_PARTNUM: $$1785048$$ERJ-3GSYJ102; MFG: PANASONIC; Notes: DNI; Part Number: ERJ-6GEY0R00V; RATING: 1/8W; SOURCE: DIGI P0.0ACT-ND; TOLERANCE: 5%
J9 = conn_120_QTH: Connector, 120 pin; MFG: SAMTEC; Part Number: QTH-060-05-L-D-A; SOURCE: SAMTEC
C17 C18 = CAP_NP: MFG: Samsung; Part Number: CL10C180JB81PNC; RATING: 50V; TOLERANCE: 5%; Type: C0G/NP0
C628 = CAP_NP: DNI: DNI; Notes: DNI
C629 C643 C651 C666 = CAP_NP: MFG: Samsung; Part Number: CL31B106MOHNNNE; TOLERANCE: 20%; Type: X7R
C625 C630-C637 C642 C644 C645 C649 C650 C652-C655 C661 C662 C664 C665 C667-C673 C677 C678 C681 C683 = CAP_NP: MFG: Samsung; Part Number: CL10B104KB8NNNC; RATING: 50V; TOLERANCE: 10%; Type: X7R
C638 C639 C646 C647 C679 = CAP_NP: MFG: Samsung; Part Number: CL10B102KB8NNNC; RATING: 50V; TOLERANCE: 10%; Type: X7R
C641 C648 C660 C663 C676 = CAP_NP: MFG: Samsung; Part Number: CL10A225KO8NNNC; RATING: 16V; TOLERANCE: 10%; Type: X5R
CN1 = HDMI_MHL_Connector_-_SMT_1: MFG: Amphenol; MFG P/N: 10029449-111RLF
D517 = rclamp0502b_1: TVS DIODE 5VWM 25VC SC75; MFG: Semtech; Part Number: RCLAMP0502BATCT; RATING: 25V / 5A
D518 = BAV70_SOT_0: BAV70 SOT23 BY PAN JIT; A/I?: SMT; MFG: Panjit; PART ID: 93L  64 42  P; Part Number: BAV70_R1_00001; RATING: 75V
D519 = rclamp0502b: TVS DIODE 5VWM 25VC SC75; MFG: Semtech; Part Number: RCLAMP0502BATCT; RATING: 25V / 5A
D520 = LED: DNI: DNI; Notes: DNI
FB1-FB9 = FerritBead: 60 Ohms @ 100 MHz 1 Ferrite Bead 0805 (2012 Metric) 3A 30mOhm-L0805; MFG: Vishay Dale; RATING: 60 ohms @ 100 MHz
J3 = HEADER_7X2: CONN HEADER VERT 14POS 2.54MM; MFG: Samtech; Part Number: TSW-107-07-F-D
R1 = RESISTOR_3_5: RES 22 OHM 5% 1/10W 0603; MFG: YAGEO; Part Number: RC0603JR-0722RL; TOLERANCE: 5%
R2 = RESISTOR_3_8: RES 22 OHM 5% 1/10W 0603; MFG: YAGEO; Part Number: RC0603JR-0722RL; TOLERANCE: 5%
R3 = RESISTOR_3_19: RES 22 OHM 5% 1/10W 0603; MFG: YAGEO; Part Number: RC0603JR-0722RL; TOLERANCE: 5%
R5 R612 = R_v2: RES 3K OHM 5% 1/10W 0603; MFG: YAGEO; Part Number: RC0603JR-073KL; TOLERANCE: 5%
R9 = RESISTOR_3_12: RES 22 OHM 5% 1/10W 0603; MFG: YAGEO; Part Number: RC0603JR-0722RL; TOLERANCE: 5%
R10 = RESISTOR_3_10: RES 22 OHM 5% 1/10W 0603; MFG: YAGEO; Part Number: RC0603JR-0722RL; TOLERANCE: 5%
R11 = RESISTOR_3_11: RES 22 OHM 5% 1/10W 0603; MFG: YAGEO; Part Number: RC0603JR-0722RL; TOLERANCE: 5%
R18 = RESISTOR_3_1: RES 22 OHM 5% 1/10W 0603; MFG: YAGEO; Part Number: RC0603JR-0722RL; TOLERANCE: 5%
R19 = RESISTOR_3_2: RES 22 OHM 5% 1/10W 0603; MFG: YAGEO; Part Number: RC0603JR-0722RL; TOLERANCE: 5%
R20 = RESISTOR_3_24: RES 22 OHM 5% 1/10W 0603; MFG: YAGEO; Part Number: RC0603JR-0722RL; TOLERANCE: 5%
R21 = RESISTOR_3_28: RES 22 OHM 5% 1/10W 0603; MFG: YAGEO; Part Number: RC0603JR-0722RL; TOLERANCE: 5%
R29 = RESISTOR: 1 MOhms ±0.1% 0.1W, 1/10W Chip Resistor 0603 (1608 Metric) Thin Film; MFG: YAGEO; Part Number: RT0603BRD071ML; RATING: 1/10W; TOLERANCE: 0.1%
R30 = RESISTOR_3_17: RES 22 OHM 5% 1/10W 0603; MFG: YAGEO; Part Number: RC0603JR-0722RL; TOLERANCE: 5%
R31 = RESISTOR_3_20: RES 22 OHM 5% 1/10W 0603; MFG: YAGEO; Part Number: RC0603JR-0722RL; TOLERANCE: 5%
R32 = RESISTOR_3_3: RES 22 OHM 5% 1/10W 0603; MFG: YAGEO; Part Number: RC0603JR-0722RL; TOLERANCE: 5%
R34 = RESISTOR_3_9: RES 22 OHM 5% 1/10W 0603; MFG: YAGEO; Part Number: RC0603JR-0722RL; TOLERANCE: 5%
R39 = RESISTOR_3_21: RES 22 OHM 5% 1/10W 0603; MFG: YAGEO; Part Number: RC0603JR-0722RL; TOLERANCE: 5%
R540 = RESISTOR_3_6: RES 0 OHM JUMPER 1/10W 0603; MFG: YAGEO; Part Number: RC0603JR-070RL
R541 R625 = R_v2: RES 1K OHM 1% 1/10W 0603; MFG: YAGEO; Part Number: RC0603FR-071KL; TOLERANCE: 1%
R542 = RESISTOR_3_23: RES 0 OHM JUMPER 1/10W 0603; MFG: YAGEO; Part Number: RC0603JR-070RL
R543 R622-R624 = R_v2: RES 4.7K OHM 1% 1/10W 0603; MFG: YAGEO; Part Number: RC0603FR-074K7L; TOLERANCE: 1%
R544 R614 R616 R617 R619-R621 = R_v2: DNI: DNI
R568 = RESISTOR_3_14: RES 22 OHM 5% 1/10W 0603; MFG: YAGEO; Part Number: RC0603JR-0722RL; TOLERANCE: 5%
R569 = RESISTOR_3_13: RES 22 OHM 5% 1/10W 0603; MFG: YAGEO; Part Number: RC0603JR-0722RL; TOLERANCE: 5%
R570 = RESISTOR_3_22: RES 22 OHM 5% 1/10W 0603; MFG: YAGEO; Part Number: RC0603JR-0722RL; TOLERANCE: 5%
R571 = RESISTOR_3_18: DNI: DNI; Notes: DNI
R572 = RESISTOR_3_29: RES 22 OHM 5% 1/10W 0603; MFG: YAGEO; Part Number: RC0603JR-0722RL; TOLERANCE: 5%
R584 = RESISTOR_3_26: RES 10K OHM 5% 1/10W 0603; MFG: YAGEO; Part Number: RC0603JR-0710KL; TOLERANCE: 5%
R585 = RESISTOR_2: RES 10K OHM 5% 1/10W 0603; MFG: YAGEO; Part Number: RC0603JR-0710KL; TOLERANCE: 5%
R589 R591 R615 R618 = R_v2: RES 33 OHM 5% 1/10W 0603; MFG: YAGEO; Part Number: RC0603JR-0733RL; TOLERANCE: 5%
R590 R594 = R_v2: DNI: DNI; Notes: DNI
R592 = R_v2: RES 100K OHM 1% 1/10W 0603; MFG: YAGEO; Part Number: RC0603FR-07100KL; TOLERANCE: 1%
R593 R628 = R_v2: RES 10K OHM 5% 1/10W 0603; MFG: YAGEO; Part Number: RC0603JR-0710KL; TOLERANCE: 5%
R595 = R_v2: RES 22 OHM 5% 1/10W 0603; MFG: YAGEO; Part Number: RC0603JR-0722RL; TOLERANCE: 5%
R601 = RESISTOR_3_4: RES 0 OHM JUMPER 1/10W 0603; MFG: YAGEO; Part Number: RC0603JR-070RL
R602 R630 = RESISTOR_3: RES 0 OHM JUMPER 1/10W 0603; MFG: YAGEO; Part Number: RC0603JR-070RL
R605 = RESISTOR_3_25: RES 22 OHM 5% 1/10W 0603; MFG: YAGEO; Part Number: RC0603JR-0722RL; TOLERANCE: 5%
R606 = RESISTOR_3_27: DNI: DNI
R607 = RESISTOR_3_30: RES 33 OHM 5% 1/10W 0603; MFG: YAGEO; Part Number: RC0603JR-0733RL; TOLERANCE: 5%
R608 = RESISTOR_3_7: RES 33 OHM 5% 1/10W 0603; MFG: YAGEO; Part Number: RC0603JR-0733RL; TOLERANCE: 5%
R609 = RESISTOR_3_16: RES 4.7K OHM 1% 1/10W 0603; MFG: YAGEO; Part Number: RC0603FR-074K7L; TOLERANCE: 1%
R610 = RESISTOR_3_15: RES 4.7K OHM 1% 1/10W 0603; MFG: YAGEO; Part Number: RC0603FR-074K7L; TOLERANCE: 1%
R611 = R_v2: RES 1.5K OHM 5% 1/10W 0603; MFG: YAGEO; Part Number: RC0603JR-071K5L; TOLERANCE: 5%
RN1 RN2 RN4 = RESARR_IS_8_SO: RES ARRAY 8 RES 22 OHM 1506; MFG: Panasonic; Part Number: EXB-2HV220JV
TP1 = TEST: DNI: DNI
U510 U511 = RClamp0514M: MFG: Semtech; MFG P/N: RCLAMP0524PATCT; Part Number: RCLAMP0524PATCT
U516 = IT6802: MFG: ITE
X1 = CRY_1: CRYSTAL 27.0000MHZ 18PF SMD; MFG: ECS Inc.; Part Number: ECS-270-18-5PX-F-TR
C605 C606 = CAP_NP: Capacitor; ICA_MFR_NAME: PANASONIC; ICA_PARTNUM: $$1755758$$ECJ-4YB1A226M; MFG: Samsung; Part Number: CL10A225KO8NNNC; RATING: 16V; SOURCE: DIGI PCC2273CT-ND; TOLERANCE: 10%; Type: X5R
C607 = CAP_NP: Capacitor; MFG: KEMET; Part Number: C0402C103J4RACTU; RATING: 16V; SOURCE: DIGI 399-1039-1-ND; TOLERANCE: 5%; Type: X7R
C608 = CAP_NP: Capacitor; DNI: DNI; MFG: Samsung; Notes: DNI; Part Number: CL05B104KO3LNNC; RATING: 16V; SOURCE: DIGI PCC13490CT-ND; TOLERANCE: 10%; Type: X7R
C623 = C_v3: MFG: YAGEO; Part Number: CC1206ZKY5V7BB106; RATING: 16v; TOLERANCE: -20%, +80%; Type: Y5V
C624 = CAP_1206: MFG: Samsung; Part Number: CL31A226MOCLNNC; RATING: 16v; TOLERANCE: 20%; Type: X5R
C626 = CAP_NP: MFG: YAGEO; Part Number: CC0603JRNPO9BN101; Rating: 50V; TOLERANCE: 5%; Type: C0G/NPO
C796 = C: CAP CER 0.1UF 50V X7R 0402; DigiKey Part Number: 445-6899-1-ND; MFG: TDK; MFG Part Number: CGA2B3X7R1H104K050BB; Manufacturer: TDK; PART NUMBER: CGA2B3X7R1H104K050BB; RATING: 50V; TOLERANCE: 10%; VOLTAGE: 50V
C797 C798 = C: CAP CER 10UF 50V X7R 1210; DIELECTRIC: X7R; Digikey Part Number: 1276-3388-1-ND; MFG: Samsung; MFG Part Number: CL32B106KBJNNWE; Manufacturer: Samsung; PART NUMBER: CL32B106KBJNNWE; Rating: 50 V; TOLERANCE: 10%; Type: X7R
C799 = C: CAP CER 0.1UF 50V X7R 0402; DNI: DNI; DigiKey Part Number: 445-6899-1-ND; MFG: TDK; MFG Part Number: CGA2B3X7R1H104K050BB; Manufacturer: TDK; Notes: DNI; PART NUMBER: CGA2B3X7R1H104K050BB; RATING: 50V; TOLERANCE: 10%; VOLTAGE: 50V
C800 = C: CAP CER 22UF 25V X5R 0805; DIELECTRIC: X5R; Digikey Part Number: 490-14661-1-ND; MFG: Murata; MFG Part Number: GRM21BR61E226ME44K; Manufacturer: Murata; Part Number: GRM21BR61E226ME44K; Rating: 25 V; TOLERANCE: 20%
C801 = C: CAP CER 22UF 25V X5R 0805; DIELECTRIC: X5R; Digikey Part Number: 490-14661-1-ND; MFG: Murata; MFG Part Number: GRM21BR61E226ME44K; Manufacturer: Murata; PART NUMBER: GRM21BR61E226ME44K; Rating: 25 V; TOLERANCE: 20%
J7 = HDR_4: Connector, 4 Pin; MFG: MOLEX; Part Number: 43045-0412; SOURCE: DIGI WM1790-ND
L502 = INDUCTOR_IRON_3.6mmx3.8mm: Part Number: 74438335047
L503 = L: MFG: Bourns; PART NUMBER: PM3316-2R2M-RC; Rating: 6.1 A; TOLERANCE: 20%
R38 R51 R54 R55 = R_v2: Resistor; ICA_MFR_NAME: PANASONIC; ICA_PARTNUM: $$1785048$$ERJ-3GSYJ102; MFG: PANASONIC; Part Number: ERJ-6GEY0R00V; RATING: 1/8W; SOURCE: DIGI P0.0ACT-ND; TOLERANCE: 5%
R50 = R_v2: Resistor; ICA_MFR_NAME: PANASONIC; ICA_PARTNUM: $$1785048$$ERJ-3GSYJ102; MFG: PANASONIC; Part Number: ERJ-6BWFR010V; RATING: 1/4W; SOURCE: DIGI P.01AQCT-ND; TOLERANCE: 1%
R52 = R_v2: Resistor; DNI: DNI; ICA_MFR_NAME: PANASONIC; ICA_PARTNUM: $$1785048$$ERJ-3GSYJ102; MFG: PANASONIC; Notes: DNI; Part Number: ERJ-2RKF1133X; RATING: 1/16W; SOURCE: DIGI P113KLCT-ND; TOLERANCE: 1%
R53 = R_v2: Resistor; DNI: DNI; ICA_MFR_NAME: PANASONIC; ICA_PARTNUM: $$1785048$$ERJ-3GSYJ102; MFG: VISHAY; Notes: DNI; Part Number: CRCW0402200KFKED; RATING: 1/16W; SOURCE: DIGI 541-200KLTR-ND; TOLERANCE: 1%
R573 = RESISTOR: Resistor; MFG: VISHAY; Part Number: CRCW040251K0FKED; RATING: 1/16W; SOURCE: DIGI P51.0KLTR-ND; TOLERANCE: 1%
R574 = R_v2: Resistor; ICA_MFR_NAME: PANASONIC; ICA_PARTNUM: $$1785048$$ERJ-3GSYJ102; MFG: VISHAY; Part Number: CRCW040229K4FKED; RATING: 1/16W; SOURCE: DIGI 541-29.4KLTR-ND; TOLERANCE: 1%
R8 R15 R509 R575 = R_v2: Resistor; ICA_MFR_NAME: PANASONIC; ICA_PARTNUM: $$1785048$$ERJ-3GSYJ102; MFG: PANASONIC; Part Number: ERJ-2GEJ332X; RATING: 1/16W; SOURCE: DIGI P3.3KJCT-ND; TOLERANCE: 5%
R586 R588 = R_v2: RES 30K OHM 5% 1/10W 0603; MFG: Yageo; Part Number: RC0603JR-0730KL; RATING: 1/10W; TOLERANCE: 5%
R629 = RESISTOR_3_2: RES 0 OHM JUMPER 1/10W 0603; DNI: DNI; MFG: YAGEO; Notes: DNI; Part Number: RC0603JR-070RL
R633 = R: RES SMD 5.76KOHM 1% 1/16W 0402; DigiKey Part Number: P13.7KDCCT-ND; MFG: Vishay Dale; MFG Part Number: CRCW04025K76FKEDC; Manufacturer: Vishay Dale; PART NUMBER: CRCW04025K76FKEDC; Rating: 1/16 W; TOLERANCE: 1%
R634 = R: RES SMD 10K OHM 1% 1/16W 0402; DigiKey Part Number: 1276-3431-1-ND; MFG: Samsung; MFG Part Number: RC1005F103CS; Manufacturer: Samsung; PART NUMBER: RC1005F103CS; POWER: 1/16 W; Rating: 0.1 W; TOLERANCE: 1%
R635 = RESISTOR_3_1: RES 0 OHM JUMPER 1/10W 0603; MFG: YAGEO; Part Number: RC0603JR-070RL
U14 = MAX5418: IC, EEPOT 100K; DNI: DNI; MFG: MAXIM; Notes: DNI; Part Number: MAX5418LETA+T; SOURCE: DIGI 296-21887-2-ND
U505 = TPS73701_0: IC, LDO Voltage Regulator; MFG: TI; Part Number: TPS73701DCQ; RATING: 1A; SOURCE: DIGI 296-19481-5-ND
U512 = IT7831TS: DNI: DNI; Notes: DNI
U518 = TPS564201: IC REG BUCK ADJ 4A TSOT23-6; Digikey Part Number: 296-44195-1-ND; MFG: Texas Instruments; MFG Part Number: TPS564201DDCT; Manufacturer: Texas Instruments; PART NUMBER: TPS564201DDCT
Q500 = 2N2222: Bipolar (BJT) Transistor NPN 40 V 600 mA 300MHz 225 mW Surface Mount SOT-23-3 (TO-236); MFG: onsemi; Part Number: MMBT2222ALT1G; SOURCE: DIGI MMBT2222AFSTR-ND
R500 = R_v2: Resistor; MFG: YAGEO; Part Number: RC0402JR-0710KL; RATING: 1/16W; SOURCE: DIGI RHM10KJTR-ND; TOLERANCE: 5%
R636 = R_v2: RES 0 OHM JUMPER 1/16W 0402; ICA_MFR_NAME: PANASONIC; ICA_PARTNUM: $$1785048$$ERJ-3GSYJ102; MFG: YAGEO; Part Number: RC0402JR-070RL; RATING: 1/16W; SOURCE: DIGI P3.3KJCT-ND; TOLERANCE: 5%
SW1 = CVS-01TB: MFG: Nidec Copal Electronics
U7 = 74CB3T3253: IC, Dual 1 of 4 bus switch; MFG: TI; Part Number: SN74CB3T3253PWR; SOURCE: DIGI 296-19156-1-ND
U8 = PCA9539: IC, I2C GPIO Expander; MFG: TI; Part Number: TCA9539PWR
U500 = 24C02_0: IC, EEPROM, 2K bit; MFG: Atmel; Part Number: AT24C02C-SSHM-B
C680 C682 = CAP_NP: MFG: Samsung; Part Number: CL10C220JB8NFNC; RATING: 50V
JP1 = HEADER_1x2_A_0: CONN HEADER VERT 2POS 2.54MM; DNI: DNI; MFG: Wurth; Part Number: 61300211121
JP2 = HEADER_3_1: CONN HEADER VERT 3POS 2.54MM; DNI: DNI; MFG: Wurth; Part Number: 61300311121
JP3 = HEADER_3: CONN HEADER VERT 3POS 2.54MM; DNI: DNI; MFG: Wurth; Part Number: 61300311121
U517 = 8051_LQFP48: DNI: DNI; Notes: DNI
Y-1 = CRYSTAL_0: DNI: DNI; Notes: DNI

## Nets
GND: C3.1 C5.1 C17.1 C18.1 C34.2 C35.2 C36.2 C37.2 C38.2 C508.1 C605.2 C606.2 C608.1 C617.2 C618.2 C619.2 C620.2 C621.2 C623.2 C624.2 C625.2 C628.2 C629.2 C630.2 C631.2 C632.2 C633.2 C634.2 C635.2 C636.2 C637.2 C638.2 C639.2 C641.2 C642.2 C643.2 C644.2 C645.2 C646.2 C647.2 C648.2 C649.2 C650.2 C651.2 C652.2 C653.2 C654.2 C655.2 C660.2 C661.2 C662.2 C663.2 C664.2 C665.2 C666.2 C667.2 C668.2 C669.2 C670.2 C671.2 C672.2 C673.2 C676.2 C677.2 C678.2 C679.2 C680.2 C682.2 C683.2 C797.1 C798.1 C800.1 C801.1 CN1.2(Shield/CD_SENSE) CN1.5(D1_Shield) CN1.8(D0_Shield) CN1.11(CK_Shield) CN1.17(GND) CN1.20(SHELL1) CN1.21(SHELL2) CN1.22(SHELL3) CN1.23(SHELL4) D517.3 D519.3 D520.2(CATHODE) J3.1 J3.3 J3.5 J3.7 J3.9 J3.11 J3.13 J6.4 J7.1 J7.3 J9.G1 J9.G2 J9.G3 J9.G4 J9.G5 J9.G6 J9.G7 J9.G8 J500.G1 J500.G2 J500.G3 J500.G4 J500.G5 J500.G6 J500.G7 J500.G8 JP1.2 JP2.2 JP3.3 MT1.1 MT2.1 MT3.1 Q500.1(EMITTER) R5.2 R52.2 R541.2 R543.1 R574.2 R588.1 R592.2 R612.2 R628.1 R634.2 SW1.2 U7.8(GND) U8.2(A1) U8.12(GND) U14.4(A0) U14.5(GND) U14.9(PAD) U500.1(A0) U500.2(A1) U500.3(A2) U500.4(VSS) U505.3(GND) U505.6(GND) U510.3 U510.8 U511.3 U511.8 U512.2(GND) U516.31(CDSENSE) U516.72(IVSS12) U516.86(OVSS) U516.96(IVSS12) U516.107(OVSS) U516.119(IVSS12) U516.129(EXPOSED_GND_PAD) U517.17(VSS) U518.1(GND)
P5V: C605.1 C623.1 C797.2 C798.2 D518.1(A2) R38.2 R55.2 R575.1 R635.2 U14.1(VDD) U505.1(IN) U512.1(EN) U512.4(VIN) U518.3(VIN)
P5V_HDMI0: C508.2 D518.3(K) R509.1 R584.2 R585.2 U500.8(VCC)
P5V_LAB: J7.4 R55.1
P5V_MAIN: C35.1 C617.1 J9.9(A5) J9.11(A6) J500.9(A5) J500.11(A6) R38.1
51_SCL: JP2.1 R622.1 U517.6(P3.0/RXD)
51_SDA: JP2.3 R623.1 U517.8(P3.1/TXD)
AFE_RSTZ: J9.108(B54) J500.108(B54) R542.2 R624.1 U8.3(RESETZ) U517.12(P3.5/T1)
ALT_PWR: J9.1(A1) R56.1
ALT_PWR2: J9.3(A2) R583.1
ALT_PWR2_MCONN: J500.3(A2) R583.2
ALT_PWR_MCONN: J500.1(A1) R56.2
BUS_SELECT: J9.89(A45) J500.89(A45) R540.2
CEC: CN1.13(CE_Remote) D519.1 R601.1 R602.2
DDCSCL0: R589.2 U516.29(DDCSCL0)
DDCSDA0: R591.2 U516.28(DDCSDA0)
DE: R570.1 U516.12(DE)
HAPS_CLK: J9.119(A60) J500.119(A60)
HDMI_0_VCC5: CN1.18(+5V) D518.2(A1) R590.1 R611.1
HDMI_CEC: J9.13(A7) J500.13(A7) R601.2
HDMI_DDC_CI_OEZ: R15.2 U7.1(~{1OE}) U7.15(~{2OE}) U8.6(P02)
HDMI_DDC_CI_S0: U7.14(S0) U8.4(P00)
HDMI_DDC_CI_S1: U7.2(S1) U8.5(P01)
HDMI_EDID_WEZ: R500.1 U8.7(P03)
HDMI_EDID_WP: Q500.3(COLLECTOR) R509.2 R636.1 U500.7(WP)
HDMI_INT: J9.91(A46) J500.91(A46) R593.1 U516.21(INT#) U517.9(P3.2/~{INT0})
HSYNC: R569.1 R572.1 U516.14(HSYNC)
I2S0_DL0_CONN: J3.10 R3.1
I2S1_DR1_CONN: J3.8 R9.1
I2S2_DL1_CONN: J3.6 R10.1
I2S3_DR2_CONN: J3.4 R11.1
I2S_SCK_CONN: J3.14 R1.1 R606.1
NC1: J9.48(B24) J500.48(B24)
NC2: J9.106(B53) J500.106(B53)
NC3: J9.107(A54) J500.107(A54)
NC4: J9.109(A55) J500.109(A55)
NC5: J9.110(B55) J500.110(B55)
NC6: J9.111(A56) J500.111(A56)
NC7: J9.112(B56) J500.112(B56)
NC8: J9.120(B60) J500.120(B60)
P0.0: R614.2 U517.40(P0.0/AD0)
P0.1: R619.2 U517.39(P0.1/AD1)
P0.2: R616.2 U517.38(P0.2/AD2)
P0.3: R617.2 U517.37(P0.3/AD3)
P1_A0: J9.65(A33) J500.65(A33) R21.2
P1_A1: J9.64(B32) J500.64(B32) R20.2
P1_A2: J9.63(A32) J500.63(A32) RN1.1
P1_A3: J9.62(B31) J500.62(B31) RN1.2
P1_A4: J9.61(A31) J500.61(A31) RN1.3
P1_A5: J9.60(B30) J500.60(B30) RN1.4
P1_A6: J9.59(A30) J500.59(A30) RN1.5
P1_A7: J9.58(B29) J500.58(B29) RN1.6
P1_A8: J9.57(A29) J500.57(A29) RN1.7
P1_A9: J9.56(B28) J500.56(B28) RN1.8
P1_ACTDATA: J9.87(A44) J500.87(A44) R570.2
P1_B0: J9.75(A38) J500.75(A38) R19.2
P1_B1: J9.74(B37) J500.74(B37) R18.2
P1_B2: J9.73(A37) J500.73(A37) RN2.1
P1_B3: J9.72(B36) J500.72(B36) RN2.2
P1_B4: J9.71(A36) J500.71(A36) RN2.3
P1_B5: J9.70(B35) J500.70(B35) RN2.4
P1_B6: J9.69(A35) J500.69(A35) RN2.5
P1_B7: J9.68(B34) J500.68(B34) RN2.6
P1_B8: J9.67(A34) J500.67(A34) RN2.7
P1_B9: J9.66(B33) J500.66(B33) RN2.8
P1_C0: J9.85(A43) J500.85(A43) R31.2
P1_C1: J9.84(B42) J500.84(B42) R30.2
P1_C2: J9.83(A42) J500.83(A42) RN4.1
P1_C3: J9.82(B41) J500.82(B41) RN4.2
P1_C4: J9.81(A41) J500.81(A41) RN4.3
P1_C5: J9.80(B40) J500.80(B40) RN4.4
P1_C6: J9.79(A40) J500.79(A40) RN4.5
P1_C7: J9.78(B39) J500.78(B39) RN4.6
P1_C8: J9.77(A39) J500.77(A39) RN4.7
P1_C9: J9.76(B38) J500.76(B38) RN4.8
P1_FIELD: J9.88(B44) J500.88(B44) R39.1 R571.2
P1_HSYNC: J9.86(B43) J500.86(B43) R569.2
P1_VSYNC: J9.55(A28) J500.55(A28) R32.2
P1P2V_MAIN: C36.1 C621.1 J9.2(B1) J9.4(B2) J500.2(B1) J500.4(B2)
P1P8V_MAIN: C37.1 C620.1 J9.6(B3) J9.8(B4) J500.6(B3) J500.8(B4)
P2.0: JP1.1 U517.19(P2.0/A8)
P2_CLK: J9.14(B7) J500.14(B7) R34.2
P2_HSYNC: J9.46(B23) J500.46(B23) R572.2
P2_VSYNC: J9.15(A8) J500.15(A8) R568.2
P2P5V_MAIN: C38.1 C619.1 J9.10(B5) J9.12(B6) J500.10(B5) J500.12(B6)
P3P3V_AFE: C3.2 C5.2 J6.3 R8.1 R15.1 R47.1 R48.1 R50.2 U7.16(VCC) U8.24(P3P3V)
P3P3V_AFE_ADJ_A: R53.1 U14.8(H)
P3P3V_AFE_ADJ_B: R52.1 U14.6(L)
P3P3V_AFE_EN: C608.2 R575.2 U505.5(EN)
P3P3V_AFE_FB: C607.1 R573.1 R574.1 U14.7(W) U505.4(FB)
P3P3V_ITE: C681.1 C683.1 FB1.2 FB2.2 FB3.2 FB4.2 R51.1 R614.1 R616.1 R617.1 R619.1 R620.2 R621.2 R622.2 R623.2 R624.2 R625.1 U517.41(VCC)
P3P3V_LAB: J7.2 R54.1
P3P3V_LAB_RES: C606.1 C607.2 R50.1 R51.2 R53.2 R54.2 R573.2 U505.2(OUT)
P3P3V_MAIN: C34.1 C618.1 J9.5(A3) J9.7(A4) J500.5(A3) J500.7(A4)
PCA9539_PU: R8.2 U8.21(A0)
PCLK: C628.1 R34.1 U516.127(PCLK)
PCSCL: R608.1 R609.2 U516.23(PCSCL)
PCSDA: R607.1 R610.2 U516.22(PCSDA)
R0X0M: CN1.9(D0-/MHL-) U511.2 U511.9 U516.40(P0_RX0N)
R0X0P: CN1.7(D0+/MHL+) U511.1 U511.10 U516.41(P0_RX0P)
R0X1M: CN1.6(D1-) U510.5 U510.6 U516.43(P0_RX1N)
R0X1P: CN1.4(D1+) U510.4 U510.7 U516.44(P0_RX1P)
R0X2M: CN1.3(D2-) U510.2 U510.9 U516.45(P0_RX2N)
R0X2P: CN1.1(D2+) U510.1 U510.10 U516.46(P0_RX2P)
R0XCM: CN1.12(CK-) U511.5 U511.6 U516.38(P0_RXCN)
R0XCP: CN1.10(CK+) U511.4 U511.7 U516.39(P0_RXCP)
RX_1V2: FB5.2 FB6.2 FB7.2 FB8.2 FB9.2 R629.2 R630.2
RX_APVDD12: C663.1 C664.1 C665.1 FB7.1 U516.65(APVDD12)
RX_AVCC12: C651.1 C652.1 C653.1 FB5.1 U516.34(AVCC12) U516.50(AVCC12)
RX_AVCC33: C643.1 C644.1 C645.1 C646.1 C647.1 C654.1 C655.1 FB3.1 U516.37(AVCC33) U516.42(AVCC33) U516.47(AVCC33) U516.53(AVCC33) U516.58(AVCC33) U516.63(APVCC33)
RX_DVDD12: C676.1 C677.1 C678.1 FB9.1 U516.48(DVDD12) U516.64(DVDD12)
RX_HPD0: CN1.19(HPD/CBUS) D519.2 R590.2 R592.1 R595.1
RX_IVDD12: C666.1 C667.1 C668.1 C669.1 C670.1 C671.1 C672.1 C673.1 FB8.1 U516.9(IVDD12) U516.24(IVDD12) U516.74(IVDD12) U516.84(IVDD12) U516.97(IVDD12) U516.110(IVDD12) U516.121(IVDD12)
RX_OVDD: C629.1 C630.1 C631.1 C632.1 C633.1 C634.1 C635.1 C636.1 C637.1 C638.1 C639.1 FB1.1 R544.1 U516.6(OVDD) U516.13(OVDD) U516.68(OVDD) U516.78(OVDD) U516.88(OVDD) U516.93(OVDD) U516.100(OVDD) U516.109(OVDD) U516.116(OVDD) U516.123(OVDD) U516.128(OVDD)
RX_OVDD33: C641.1 C642.1 FB2.1 R593.2 R609.1 R610.1 U516.32(OVDD33)
RX_PVCC12: C660.1 C661.1 C662.1 FB6.1 U516.35(PVCC12) U516.51(PVCC12)
RX_PVCC33: C648.1 C649.1 C650.1 FB4.1 U516.36(PVCC33) U516.52(PVCC33)
SCL_0: J6.1 J9.115(A58) J500.115(A58) JP3.1 R48.2 R608.2 R618.2 U7.6(1B1) U8.22(SCL) U14.2(SCL)
SCL_DDC_CI_1: J9.95(A48) J500.95(A48) U7.5(1B2)
SCL_DDC_CI_2: J9.113(A57) J500.113(A57) U7.4(1B3)
SCL_HDMI0_DDC_CI: CN1.15(DDC_CLK/CD_P_UP) D517.2 R585.1 R589.1 U7.7(1A) U500.6(SCL)
SDA_0: J6.2 J9.117(A59) J500.117(A59) JP3.2 R47.2 R607.2 R615.2 U7.10(2B1) U8.23(SDA) U14.3(SDA)
SDA_DDC_CI_1: J9.93(A47) J500.93(A47) U7.11(2B2)
SDA_DDC_CI_2: J9.114(B57) J500.114(B57) U7.12(2B3)
SDA_HDMI0_DDC_CI: CN1.16(DDC_DATA) D517.1 R584.1 R591.1 U7.9(2A) U500.5(SDA)
SPDIF_DL2: J3.2 R605.1
SYSRSTN: R540.1 R542.1 U516.83(SYSRSTN)
UART_RX: J9.92(B46) J500.92(B46)
UART_TX: J9.53(A27) J500.53(A27)
VSYNC: R32.1 R568.1 U516.15(VSYNC)
WS_DR0_CONN: J3.12 R2.1
XTAL1: C680.1 U517.16(XTAL1) Y-1.2
XTAL2: C682.1 U517.15(XTAL2) Y-1.1
N17176927: C17.2 R29.1 U516.66(XTALOUT) X1.1
N17176943: C18.2 R29.2 U516.67(XTALIN) X1.2
N17208762: C679.1 R611.2 R612.1 U516.30(R0PWR5V)
N17213119: R11.2 U516.77(I2S3_DR2)
N17213121: R10.2 U516.76(I2S2_DL1)
N17213123: R9.2 U516.75(I2S1_DR1)
N17213125: R3.2 U516.73(I2S0_DL0)
N17213127: R2.2 U516.79(WS_DR0)
N17213129: R1.2 U516.80(SCK_DCLK)
N17216227: R606.2 U516.81(MCLK)
N17284357: R605.2 U516.71(SPDIF_DL2)
N17675272: R21.1 U516.102(QE26)
N17675274: R20.1 U516.101(QE27)
N17675276: RN1.16 U516.99(QE28)
N17675278: RN1.15 U516.98(QE29)
N17675280: RN1.14 U516.95(QE30)
N17675282: RN1.13 U516.94(QE31)
N17675284: RN1.12 U516.92(QE32)
N17675286: RN1.11 U516.91(QE33)
N17675288: RN1.10 U516.90(QE34)
N17675290: RN1.9 U516.89(QE35)
N17726793: R5.1 U516.27(R1PWR5V)
N17741544: R543.2 R544.2 U516.87(PCADR)
N17791476: R571.1 U516.16(EVENODD)
N17816955: R594.1 U516.85(SCDT)
N17949374: R541.1 U516.82(ENTEST)
N17950232: TP1.1(TP) U516.18(SIP_VDD)
N17950739: R595.2 U516.33(CBUS/HPD)
N17954990: R602.1 U516.20(CEC)
N17966004: D520.1(ANODE) R594.2
N18010922: RN2.15 U516.114(QE17)
N18010926: RN2.16 U516.115(QE16)
N18010974: R18.1 U516.117(QE15)
N18010978: R19.1 U516.118(QE14)
N18011121: RN2.14 U516.113(QE18)
N18011123: RN2.13 U516.112(QE19)
N18011125: RN2.12 U516.111(QE20)
N18011127: RN2.11 U516.108(QE21)
N18011129: RN2.10 U516.106(QE22)
N18011131: RN2.9 U516.105(QE23)
N18011461: RN4.15 U516.4(QE5)
N18011465: RN4.16 U516.5(QE4)
N18011513: R30.1 U516.7(QE3)
N18011517: R31.1 U516.8(QE2)
N18011660: RN4.14 U516.3(QE6)
N18011662: RN4.13 U516.2(QE7)
N18011664: RN4.12 U516.1(QE8)
N18011666: RN4.11 U516.126(QE9)
N18011668: RN4.10 U516.125(QE10)
N18011670: RN4.9 U516.124(QE11)
N28326141: C681.2 R628.2 U517.5(RST)
N28326313: R621.1 U517.3(P1.6)
N28326316: R625.2 U517.32(V30)
N28326449: R620.1 U517.2(P1.5)
N28326927: R618.1 U517.43(T2.P1.0)
N28326930: R615.1 U517.44(T2EX.P1.1)
N28358514: R39.2 U516.70(DSD_DL3_3DR)
N28473624: C626.1 R586.1 R588.2 U512.5(FB)
N28473663: L502.1 U512.3(SW)
N28473665: C624.1 C625.1 C626.2 L502.2 R586.2 R629.1
N28473777: C799.1 C800.2 C801.2 L503.2 R630.1 R633.1
N28473833: C796.2 U518.6(VBST)
N28473835: C796.1 L503.1 U518.2(SW)
N28473849: R635.1 U518.5(EN)
N28473875: C799.2 R633.2 R634.1 U518.4(VFB)
N28612814: Q500.2(BASE) R500.2
N28612873: R636.2 SW1.1

Not connected (* = marked no-connect by the designer): CN1 14(NC)*; J9 16(B8)* 17(A9)* 18(B9)* 19(A10)* 20(B10)* 21(A11)* 22(B11)* 23(A12)* 24(B12)* 25(A13)* 26(B13)* 27(A14)* 28(B14)* 29(A15)* 30(B15)* 31(A16)* 32(B16)* 33(A17)* 34(B17)* 35(A18)* 36(B18)* 37(A19)* 38(B19)* 39(A20)* 40(B20)* 41(A21)* 42(B21)* 43(A22)* 44(B22)* 45(A23)* 47(A24)* 49(A25)* 50(B25)* 51(A26)* 52(B26)* 54(B27)* 90(B45)* 94(B47)* 96(B48)* 97(A49)* 98(B49)* 99(A50)* 100(B50)* 101(A51)* 102(B51)* 103(A52)* 104(B52)* 105(A53)* 116(B58)* 118(B59)*; J500 16(B8)* 17(A9)* 18(B9)* 19(A10)* 20(B10)* 21(A11)* 22(B11)* 23(A12)* 24(B12)* 25(A13)* 26(B13)* 27(A14)* 28(B14)* 29(A15)* 30(B15)* 31(A16)* 32(B16)* 33(A17)* 34(B17)* 35(A18)* 36(B18)* 37(A19)* 38(B19)* 39(A20)* 40(B20)* 41(A21)* 42(B21)* 43(A22)* 44(B22)* 45(A23)* 47(A24)* 49(A25)* 50(B25)* 51(A26)* 52(B26)* 54(B27)* 90(B45)* 94(B47)* 96(B48)* 97(A49)* 98(B49)* 99(A50)* 100(B50)* 101(A51)* 102(B51)* 103(A52)* 104(B52)* 105(A53)* 116(B58)* 118(B59)*; U7 3(1B4)* 13(2B4)*; U8 1(INTZ)* 8(P04)* 9(P05)* 10(P06)* 11(P07)* 13(P10)* 14(P11)* 15(P12)* 16(P13)* 17(P14)* 18(P15)* 19(P16)* 20(P17)*; U516 10(QE1)* 11(QE0)* 17(NC)* 19(ENVBUS#)* 25(DDCSDA1)* 26(DDCSCL1)* 49(NC)* 54(P1_RXCN)* 55(P1_RXCP)* 56(P1_RX0N)* 57(P1_RX0P)* 59(P1_RX1N)* 60(P1_RX1P)* 61(P1_RX2N)* 62(P1_RX2P)* 69(MUTE_DR3)* 103(QE25)* 104(QE24)* 120(QE13)* 122(QE12)*; U517 1(P4.7)* 4(P1.7)* 7(/INT2.P4.3)* 10(P3.3/~{INT1})* 11(P3.4/T0)* 13(P3.6/~{WR})* 14(P3.7/~{RD})* 18(P4.0)* 20(P2.1/A9)* 21(P2.2/A10)* 22(P2.3/A11)* 23(P2.4/A12)* 24(P4.4)* 25(P4.5)* 26(P2.5/A13)* 27(P2.6/A14)* 28(P2.7/A15)* 29(OCD_SCL)* 30(OCD_SDA)* 31(P4.1)* 33(P0.7/AD7)* 34(P0.6/AD6)* 35(P0.5/AD5)* 36(P0.4/AD4)* 42(/INT3.P4.2)* 45(P1.2)* 46(P1.3)* 47(P1.4)* 48(P4.6)*

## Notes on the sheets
sheet 3
- NOTES, UNLESS OTHERWISE SPECIFIED:
- 1.
- A "Z" suffix on a signal name indicates an active low signal.
- 2.
- All components with designators "U*", "Q*", and "D*" are electrostatic discharge sensitive.
- 3.
- All components with designators above 500 are mounted solder side of the board.
- 4.
- All resistor values are in ohms, 1/16 W and 5% unless otherwise specified.
- 5.
- All capacitor values in microfarads unless otherwise specified.
- ???
- ???
sheet 4
- BLOCK DIAGRAM
- HDMI
- EDID
- I2C
- (sheet 7)
- MAIN
  BOARD
  INTERFACE
- S
  H
  3
- S
  H
  5
- HDMI/MHL
- IT6802
- S
  H
  5
- (sheets 5)
- INDEX
- S
  H
  5
- HDMI
- Sheet 1 : Cover
- Sheet 2 : Block Diagram
- Sheet 3 : Connector Main
- Sheet 4 : Connector Expansion
- Sheet 5 : HDMI Input
- Sheet 6 : Input Power
- 3.3V
- Sheet 7 : EDID
- Sheet 8 : MCU
- 1.2V
- POWER
- Sheet 9 : Rev History
- 5V
- (sheet 6)
- Sheet 10 : Important Notice
sheet 5
- FORMATTER BOARD INTERFACE CONNECTOR
- CCA MOUNTING HOLES
- Main Board Interface
sheet 6
- EXPANSION CONNECTOR
- Expansion Interface
sheet 7
- Top side
- I2C and Video bus are 3.3V level, so
  no level shifters, ( RX_OVDD= 3.3V)
- PCSCL and PCSDA level is same as
  OVDD voltage level. The level
  shifts are necessary if the
  levels of both are different.
sheet 8
- These components are for characterization only.
  They are not required for production designs
- I2C NONVOLITILE POTENTIOMETER
  I2C ADDRESS CONFIGURATION
  A0 low, address = 50h
- 1.2V for
  IT6802
- Only Install either U512 or U518.
- IT6802 and main-chip shell use
  same  I/O power for better signal
  return paths
- INPUT POWER
sheet 9
- GPIO EXPANDER I2C ADDRESS CONFIGURATION
  A1 low and A0 high, address = EAh
- HDMI EDID INTERFACE
- 3
- 2
- 1
- MMBT2222A
sheet 10
- JP1 short: Hold MCU
- Top Side
- Top Side
- PCSCL
- PCSDA
- 8051 ISP programming port
- Command port
